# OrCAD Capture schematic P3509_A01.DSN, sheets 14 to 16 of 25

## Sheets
14 0011_BUTTON MCU: size Custom
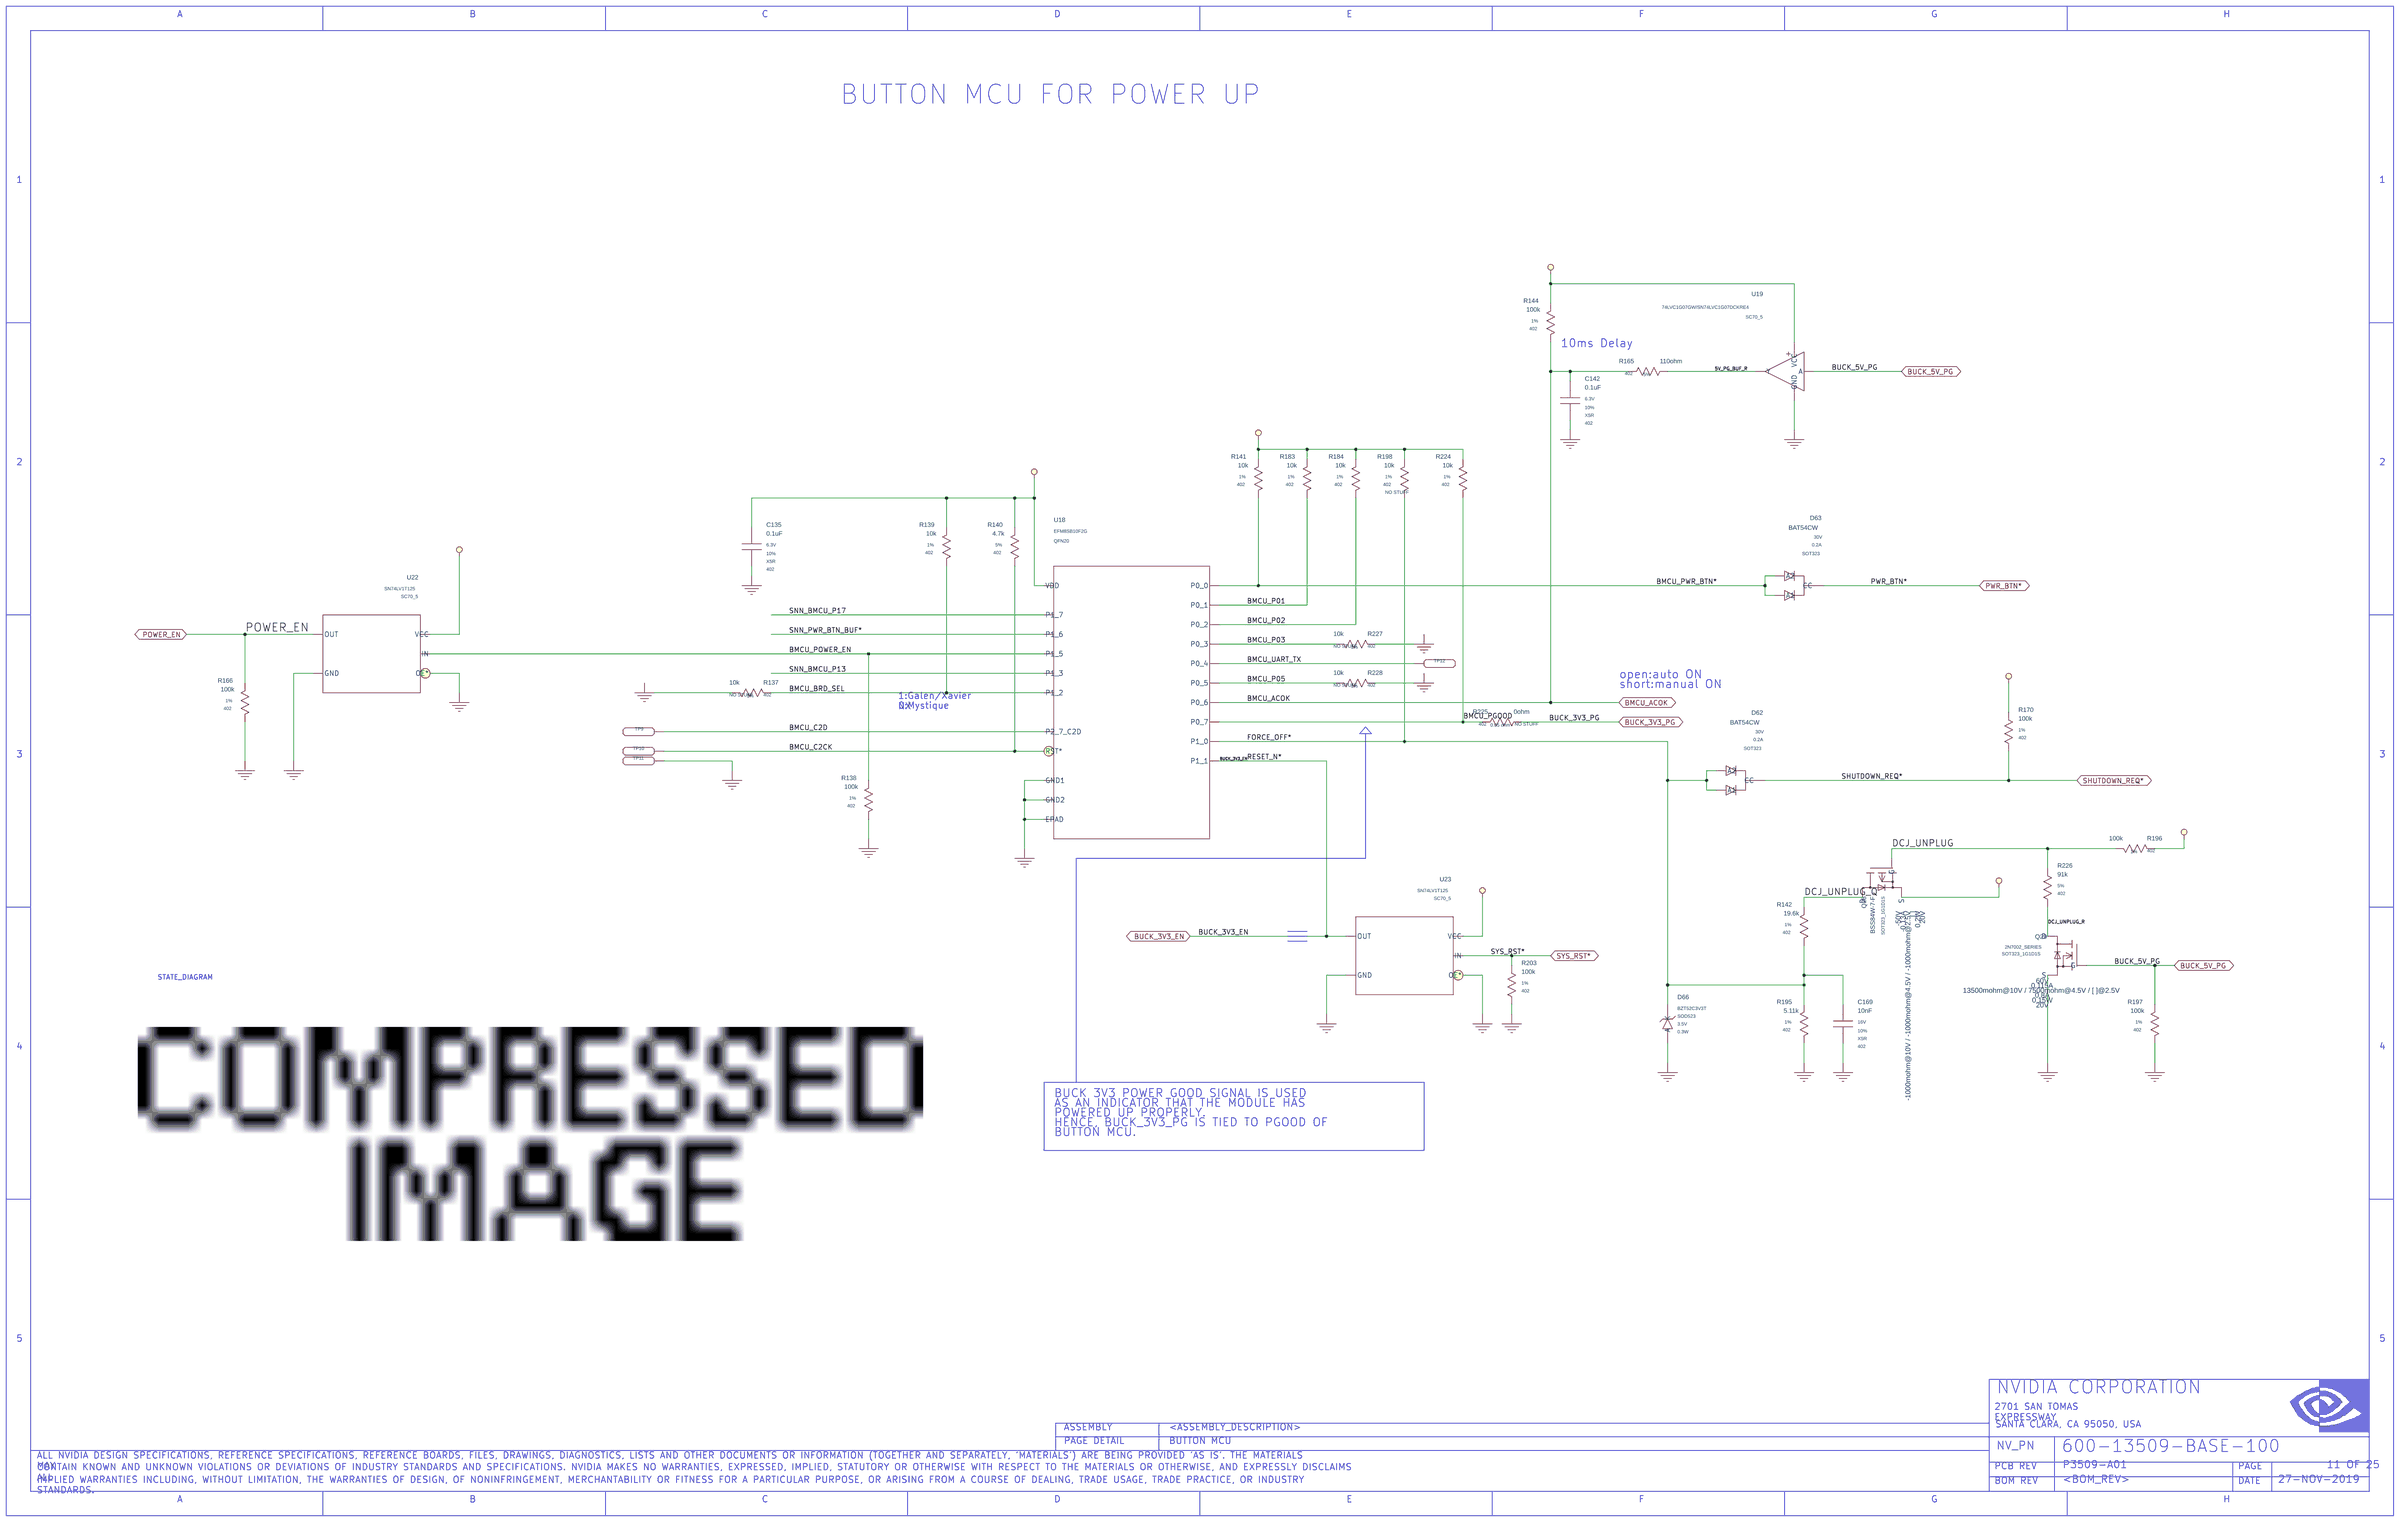
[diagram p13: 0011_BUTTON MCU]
15 0010_1V8 LDO & 3V3 AO Rails: size Custom
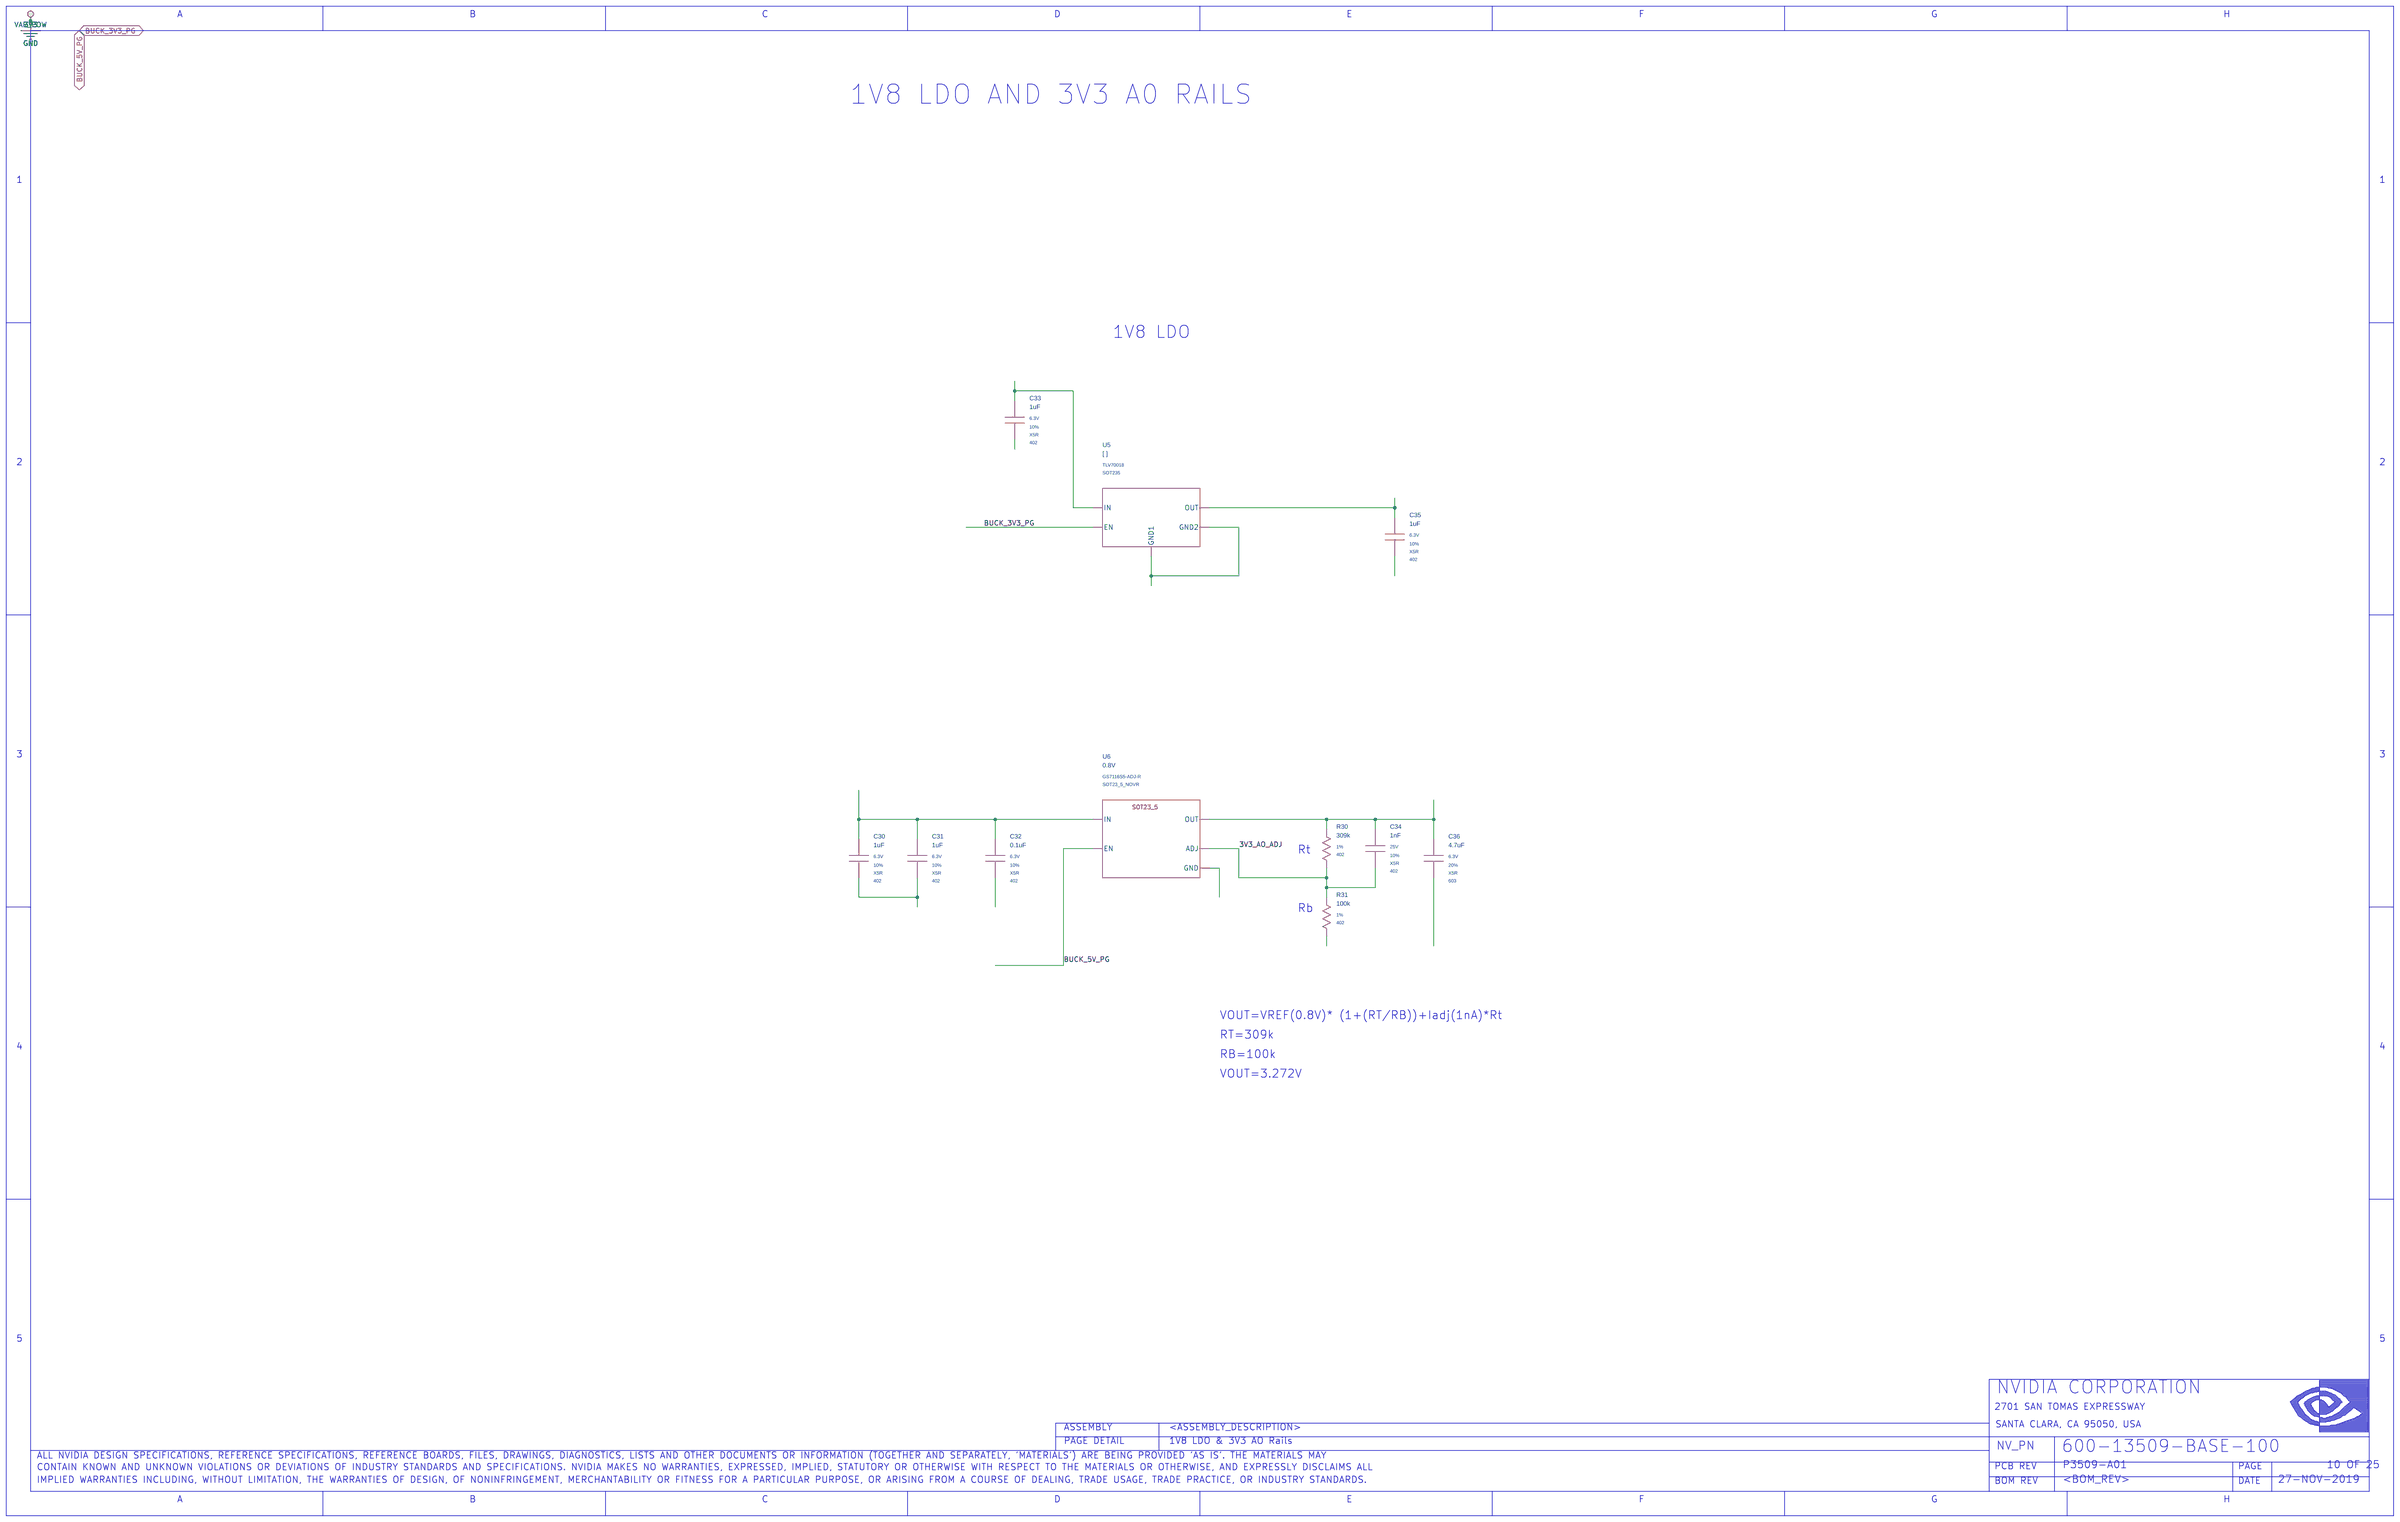
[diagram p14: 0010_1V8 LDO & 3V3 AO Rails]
16 0009_PRE-REG 3V3: size Custom
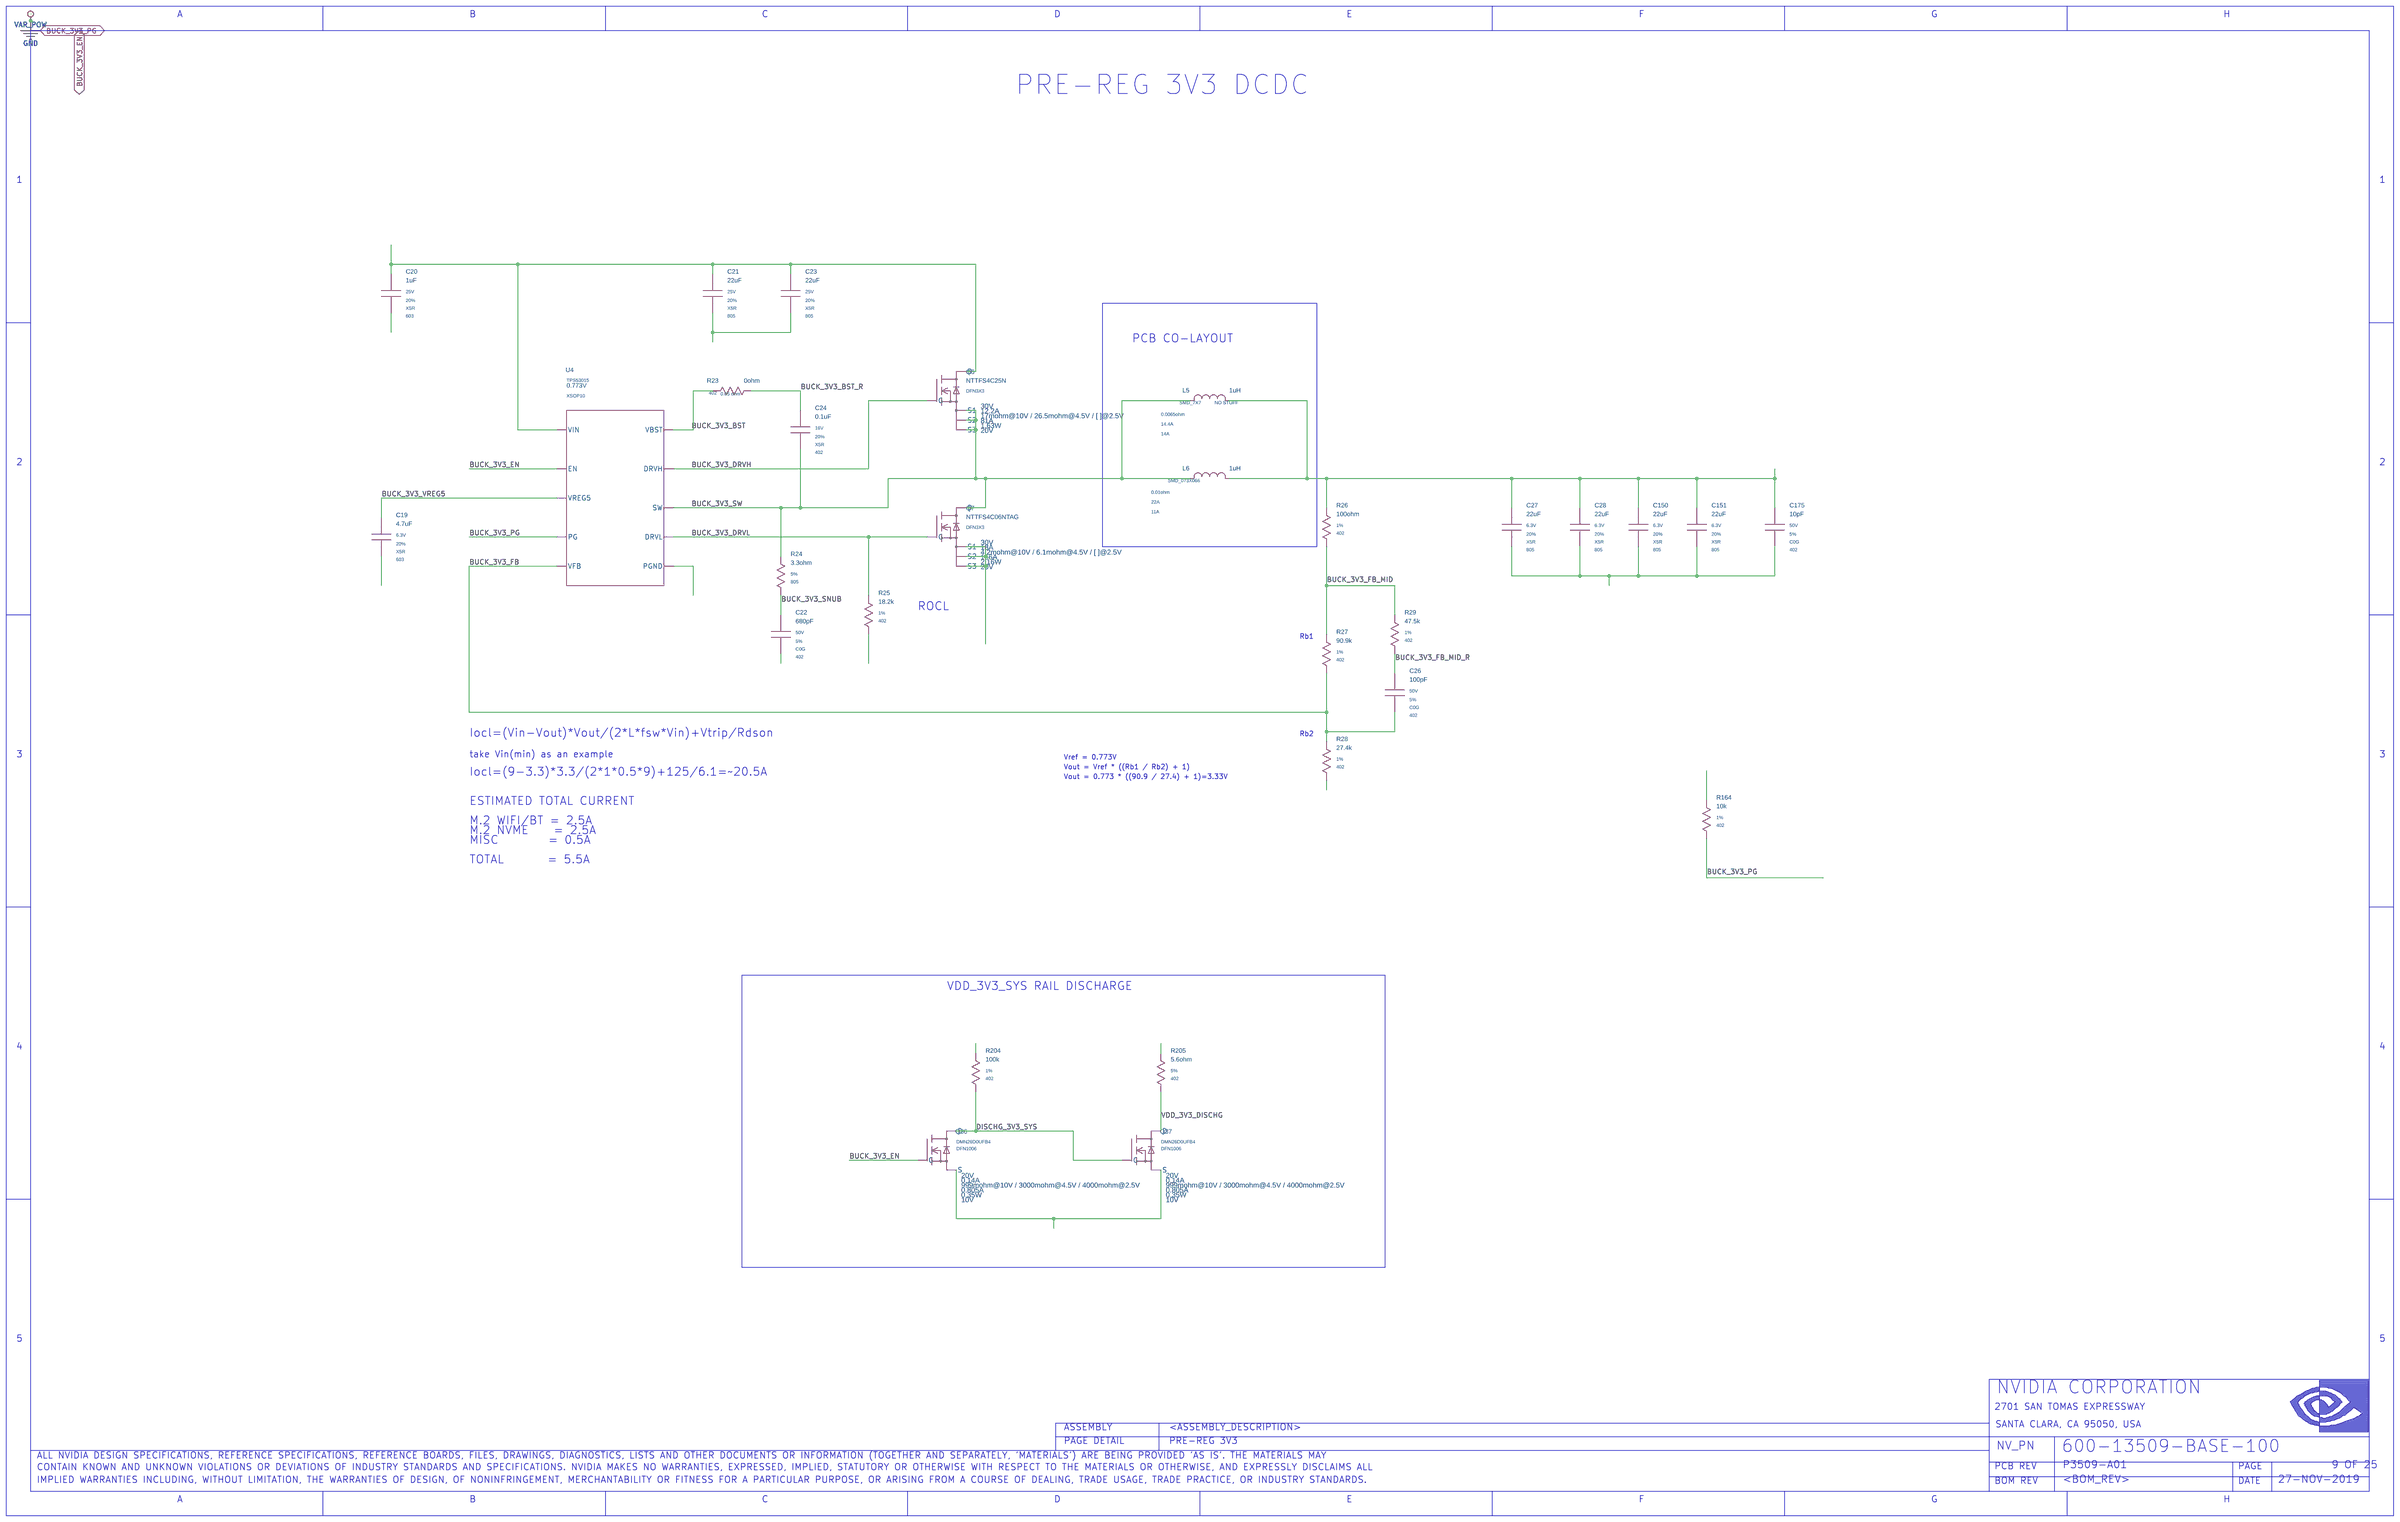
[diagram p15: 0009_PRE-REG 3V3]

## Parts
sheet 0009_PRE-REG 3V3
C19  4.7uF  [603]
C20  1uF  [603]
C21  22uF  [805]
C22  680pF  [402]
C23  22uF  [805]
C24  0.1uF  [402]
C26  100pF  [402]
C27  22uF  [805]
C28  22uF  [805]
C150  22uF  [805]
C151  22uF  [805]
C175  10pF  [402]
L5  1uH  [IND_NONRKO_SMD_071X065]
L6  1uH  [IND_NONRKO_SMD_073X066]
Q6  Q_FET_N_ENH  [MULTI_SMD_DFN08_SON08]
Q7  Q_FET_N_ENH  [MULTI_SMD_DFN08_SON08]
Q36  Q_FET_N_ENH  [DFET_003_SMD_010X006_B]
Q37  Q_FET_N_ENH  [DFET_003_SMD_010X006_B]
R23  0ohm  [402]
R24  3.3ohm  [805]
R25  18.2k  [402]
R26  100ohm  [402]
R27  90.9k  [402]
R28  27.4k  [402]
R29  47.5k  [402]
R164  10k  [402]
R204  100k  [402]
R205  5.6ohm  [402]
U4  0.773V  [XSOP10_P050_030X030]
sheet 0010_1V8 LDO & 3V3 AO Rails
C30  1uF  [402]
C31  1uF  [402]
C32  0.1uF  [402]
C33  1uF  [402]
C34  1nF  [402]
C35  1uF  [402]
C36  4.7uF  [603]
R30  309k  [402]
R31  100k  [402]
U5  [ ]  [SOT23_5]
U6  0.8V  [SOT23_5]
sheet 0011_BUTTON MCU
C135  0.1uF  [402]
C142  0.1uF  [402]
C169  10nF  [402]
D62  D_3PIN_CC  [SOT323]
D63  D_3PIN_CC  [SOT323]
D66  D_ZENER  [DIODE_SMD_SOD523_B]
Q28  Q_FET_P_ENH  [SOT323]
Q29  Q_FET_N_ENH  [SOT323]
R137  10k  [402]
R138  100k  [402]
R139  10k  [402]
R140  4.7k  [402]
R141  10k  [402]
R142  19.6k  [402]
R144  100k  [402]
R165  110ohm  [402]
R166  100k  [402]
R170  100k  [402]
R183  10k  [402]
R184  10k  [402]
R195  5.11k  [402]
R196  100k  [402]
R197  100k  [402]
R198  10k  [402]
R203  100k  [402]
R224  10k  [402]
R225  0ohm  [402]
R226  91k  [402]
R227  10k  [402]
R228  10k  [402]
TP9  LABTESTPOINT  [LTPT089C125D]
TP10  LABTESTPOINT  [LTPT089C125D]
TP11  LABTESTPOINT  [LTPT089C125D]
TP12  LABTESTPOINT  [LTPT089C125D]
U18  U_CPU_EFM8SB1  [QFN020Q_P050_0030_T018X018]
U19  U_BUF_OD  [SC70_5]
U22  U_LEVSHFT_3STATE  [SC70_5]
U23  U_LEVSHFT_3STATE  [SC70_5]

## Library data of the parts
C19 = C#1_v2: ASSEMBLY: PS_3V3; CDS_LIB: discrete; CDS_PART_NAME: C_0603-4.7UF,X5R,20%,6.3V,032-0886-000; CDS_PHYS_PART_NAME: C_0603-4.7UF,X5R,20%,6.3V,032-0886-000-032-0886-000,4.7UF; CDS_SEC: 1; CHIPS_PART_NAME: C; DEVICE_TYPENAME: C_0603-47UFX5R2063V032-0886-000-032-0886-00047UF; DRAWING: #NAME?; ESL: N/A; ESR: N/A; MAT: X5R; MAX_VOLTAGE: 6.3V; NV_PN: 032-0886-000; PATH: I34; PHYS_PAGE: 9; ROT: 0; SEC: 1; SIGNAL_MODEL: nv_cap; TOL: 20%; VER: 1; XY: (-10200,4900)
C20 = C#1_v2: ASSEMBLY: PS_3V3; CDS_LIB: discrete; CDS_PART_NAME: C_0603-1UF,X5R,20%,25V,032-0882-000; CDS_PHYS_PART_NAME: C_0603-1UF,X5R,20%,25V,032-0882-000-032-0882-000,1UF; CDS_SEC: 1; CHIPS_PART_NAME: C; DEVICE_TYPENAME: C_0603-1UFX5R2025V032-0882-000-032-0882-0001UF; DRAWING: #NAME?; MAT: X5R; MAX_VOLTAGE: 25V; NV_PN: 032-0882-000; PATH: I30; PHYS_PAGE: 9; ROT: 0; SEC: 1; SIGNAL_MODEL: nv_cap; TOL: 20%; VER: 1; XY: (-10150,6150)
C21 = C#1_v2: ASSEMBLY: PS_3V3; CDS_LIB: discrete; CDS_PART_NAME: C_0805-22UF,X5R,20%,25V,032-1308-000; CDS_PHYS_PART_NAME: C_0805-22UF,X5R,20%,25V,032-1308-000-032-1308-000,22UF; CDS_SEC: 1; CHIPS_PART_NAME: C; DEVICE_TYPENAME: C_0805-22UFX5R2025V032-1308-000-032-1308-00022UF; DRAWING: #NAME?; MAT: X5R; MAX_VOLTAGE: 25V; NV_PN: 032-1308-000; PATH: I13; PHYS_PAGE: 9; ROT: 0; SEC: 1; SIGNAL_MODEL: nv_cap; TOL: 20%; VER: 1; XY: (-8500,6150)
C22 = C#1_v2: ASSEMBLY: PS_3V3; CDS_LIB: discrete; CDS_PART_NAME: C_0402-680PF,C0G,5%,50V,035-0296-000; CDS_PHYS_PART_NAME: C_0402-680PF,C0G,5%,50V,035-0296-000-035-0296-000,680PF; CDS_SEC: 1; CHIPS_PART_NAME: C; DEVICE_TYPENAME: C_0402-680PFC0G550V035-0296-000-035-0296-000680PF; DRAWING: #NAME?; MAT: C0G; MAX_VOLTAGE: 50V; NV_PN: 035-0296-000; PATH: I26; PHYS_PAGE: 9; ROT: 0; SEC: 1; SIGNAL_MODEL: nv_cap; TOL: 5%; VER: 1; XY: (-8150,4400)
C23 = C#1_v2: ASSEMBLY: PS_3V3; CDS_LIB: discrete; CDS_PART_NAME: C_0805-22UF,X5R,20%,25V,032-1308-000; CDS_PHYS_PART_NAME: C_0805-22UF,X5R,20%,25V,032-1308-000-032-1308-000,22UF; CDS_SEC: 1; CHIPS_PART_NAME: C; DEVICE_TYPENAME: C_0805-22UFX5R2025V032-1308-000-032-1308-00022UF; DRAWING: #NAME?; MAT: X5R; MAX_VOLTAGE: 25V; NV_PN: 032-1308-000; PATH: I11; PHYS_PAGE: 9; ROT: 0; SEC: 1; SIGNAL_MODEL: nv_cap; TOL: 20%; VER: 1; XY: (-8100,6150)
C24 = C#1_v2: ASSEMBLY: PS_3V3; CDS_LIB: discrete; CDS_PART_NAME: C_0402-0.1UF,X5R,20%,16V,032-0877-000; CDS_PHYS_PART_NAME: C_0402-0.1UF,X5R,20%,16V,032-0877-000-0.1UF,032-0877-000; CDS_SEC: 1; CHIPS_PART_NAME: C; DEVICE_TYPENAME: C_0402-01UFX5R2016V032-0877-000-01UF032-0877-000; DRAWING: #NAME?; MAT: X5R; MAX_VOLTAGE: 16V; NV_PN: 032-0877-000; PATH: I12; PHYS_PAGE: 9; ROT: 0; SEC: 1; TOL: 20%; VER: 1; XY: (-8050,5450)
C26 = C#1_v2: ASSEMBLY: PS_3V3; CDS_LIB: discrete; CDS_PART_NAME: C_0402-100PF,C0G,5%,50V,035-0012-000; CDS_PHYS_PART_NAME: C_0402-100PF,C0G,5%,50V,035-0012-000-035-0012-000,100PF; CDS_SEC: 1; CHIPS_PART_NAME: C; DEVICE_TYPENAME: C_0402-100PFC0G550V035-0012-000-035-0012-000100PF; DRAWING: #NAME?; MAT: C0G; MAX_VOLTAGE: 50V; NV_PN: 035-0012-000; PATH: I19; PHYS_PAGE: 9; ROT: 0; SEC: 1; SIGNAL_MODEL: nv_cap; TOL: 5%; VER: 1; XY: (-5000,4100)
C27 = C#1_v2: ASSEMBLY: PS_3V3; CDS_LIB: discrete; CDS_PART_NAME: C_0805-22UF,X5R,20%,6.3V,039-0127-000; CDS_PHYS_PART_NAME: C_0805-22UF,X5R,20%,6.3V,039-0127-000-039-0127-000,22UF; CDS_SEC: 1; CHIPS_PART_NAME: C; DEVICE_TYPENAME: C_0805-22UFX5R2063V039-0127-000-039-0127-00022UF; DRAWING: #NAME?; MAT: X5R; MAX_VOLTAGE: 6.3V; NV_PN: 039-0127-000; PATH: I6; PHYS_PAGE: 9; ROT: 0; SEC: 1; SIGNAL_MODEL: nv_cap; TOL: 20%; VER: 1; XY: (-4400,4950)
C28 = C#1_v2: ASSEMBLY: PS_3V3; CDS_LIB: discrete; CDS_PART_NAME: C_0805-22UF,X5R,20%,6.3V,039-0127-000; CDS_PHYS_PART_NAME: C_0805-22UF,X5R,20%,6.3V,039-0127-000-039-0127-000,22UF; CDS_SEC: 1; CHIPS_PART_NAME: C; DEVICE_TYPENAME: C_0805-22UFX5R2063V039-0127-000-039-0127-00022UF; DRAWING: #NAME?; MAT: X5R; MAX_VOLTAGE: 6.3V; NV_PN: 039-0127-000; PATH: I5; PHYS_PAGE: 9; ROT: 0; SEC: 1; SIGNAL_MODEL: nv_cap; TOL: 20%; VER: 1; XY: (-4050,4950)
C150 = C#1_v2: ASSEMBLY: PS_3V3; CDS_LIB: discrete; CDS_PART_NAME: C_0805-22UF,X5R,20%,6.3V,039-0127-000; CDS_PHYS_PART_NAME: C_0805-22UF,X5R,20%,6.3V,039-0127-000-039-0127-000,22UF; CDS_SEC: 1; CHIPS_PART_NAME: C; DEVICE_TYPENAME: C_0805-22UFX5R2063V039-0127-000-039-0127-00022UF; DRAWING: #NAME?; MAT: X5R; MAX_VOLTAGE: 6.3V; NV_PN: 039-0127-000; PATH: I41; PHYS_PAGE: 9; ROT: 0; SEC: 1; SIGNAL_MODEL: nv_cap; TOL: 20%; VER: 1; XY: (-3750,4950)
C151 = C#1_v2: ASSEMBLY: PS_3V3; CDS_LIB: discrete; CDS_PART_NAME: C_0805-22UF,X5R,20%,6.3V,039-0127-000; CDS_PHYS_PART_NAME: C_0805-22UF,X5R,20%,6.3V,039-0127-000-039-0127-000,22UF; CDS_SEC: 1; CHIPS_PART_NAME: C; DEVICE_TYPENAME: C_0805-22UFX5R2063V039-0127-000-039-0127-00022UF; DRAWING: #NAME?; MAT: X5R; MAX_VOLTAGE: 6.3V; NV_PN: 039-0127-000; PATH: I42; PHYS_PAGE: 9; ROT: 0; SEC: 1; SIGNAL_MODEL: nv_cap; TOL: 20%; VER: 1; XY: (-3450,4950)
C175 = C#1_v2: ASSEMBLY: PS_3V3; CDS_LIB: discrete; CDS_PART_NAME: C_0402-10PF,C0G,5%,50V,035-0011-000; CDS_PHYS_PART_NAME: C_0402-10PF,C0G,5%,50V,035-0011-000-035-0011-000,10PF; CDS_SEC: 1; CHIPS_PART_NAME: C; DEVICE_TYPENAME: C_0402-10PFC0G550V035-0011-000-035-0011-00010PF; DRAWING: #NAME?; MAT: C0G; MAX_VOLTAGE: 50V; NV_PN: 035-0011-000; PATH: I45; PHYS_PAGE: 9; ROT: 0; SEC: 1; SIGNAL_MODEL: nv_cap; TOL: 5%; VER: 1; XY: (-3050,4950)
L5 = L: ASSEMBLY: PS_3V3; CDS_LIB: discrete; CDS_PART_NAME: L_SMD_7X7-1UH,IRON POWDER CORE,20%,14A,14.4A,0.0065OHM,0@0HZ,3MHZ,130-0996-000; CDS_PHYS_PART_NAME: L_SMD_7X7-1UH,IRON POWDER CORE,20%,14A,14.4A,0.0065OHM,0@0HZ,3MHZ,130-0996-000-130-0996-000,1UH; CDS_SEC: 1; CONTINUOUS_CURRENT: 14A; DC_RESISTANCE: 0.0065ohm; DEVICE_TYPENAME: L_SMD_7X7-1UHIRONPOWDERCORE2014A144A00065OHM00HZ3MHZ130-0996-000-130-0996-0001UH; DRAWING: #NAME?; MAT: Iron powder core; MAX_CURRENT: 14.4A; NV_PN: 130-0996-000; PACK_TYPE: SMD_7X7; PATH: I7; PHYS_PAGE: 9; Q: 0@0Hz; ROT: 0; SEC: 1; SELF_RESONANCE_FREQ: 3MHz; SIGNAL_MODEL: nv_ind; SKU: NO STUFF; TOL: 20%; VER: 1; XY: (-5950,5600)
L6 = L: ASSEMBLY: PS_3V3; CDS_LIB: discrete; CDS_PART_NAME: L_SMD_073X066-1UH,CARBONYL POWDER,20%,11A,22A,0.01OHM,[ ]@[ ],[ ],130-0776-000; CDS_PHYS_PART_NAME: L_SMD_073X066-1UH,CARBONYL POWDER,20%,11A,22A,0.01OHM,[ ]@[ ],[ ],130-0776-000-130-0776-000,1UH; CDS_SEC: 1; CONTINUOUS_CURRENT: 11A; DC_RESISTANCE: 0.01ohm; DEVICE_TYPENAME: L_SMD_073X066-1UHCARBONYLPOWDER2011A22A001OHM130-0776-000-130-0776-0001UH; DRAWING: #NAME?; MAT: Carbonyl Powder; MAX_CURRENT: 22A; NV_PN: 130-0776-000; PACK_TYPE: SMD_073X066; PATH: I8; PHYS_PAGE: 9; Q: [ ]@[ ]; ROT: 0; SEC: 1; SELF_RESONANCE_FREQ: [ ]; SIGNAL_MODEL: nv_ind; TOL: 20%; VER: 1; XY: (-5950,5200)
Q6 = Q_FET_N_ENH#2: ASSEMBLY: PS_3V3; CDS_LIB: discrete; CDS_PART_NAME: Q_FET_N_ENH_DFN3X3-NTTFS4C25N,30V,17MOHM@10V / 26.5MOHM@4.5V / [ ]@2.5V,12.2A,81A,20V,1.63W,10.3NC@10V / 5.1NC@4.5V / [ ]@2.5VA; CDS_PHYS_PART_NAME: Q_FET_N_ENH_DFN3X3-NTTFS4C25N,30V,17MOHM@10V / 26.5MOHM@4.5V / [ ]@2.5V,12.2A,81A,20V,1.63W,10.3NC@10V / 5.1NC@4.5V / [ ]@2.5VB; CDS_SEC: 1; CONTINUOUS_CURRENT: 12.2A; DEVICE_TYPENAME: Q_FET_N_ENH_DFN3X3-NTTFS4C25N30V17MOHM10V265MOHM45V25V122A81A20V163W103NC10V51NC45V25VB; DRAWING: #NAME?; MAX_CURRENT: 81A; MAX_VOLTAGE: 30V; MAX_WATTAGE: 1.63W; NV_NAME: NTTFS4C25N; NV_PN: 300-1021-000; PACK_TYPE: DFN3X3; PATH: I9; PHYS_PAGE: 9; Q_G: 10.3nC@10V / 5.1nC@4.5V / [ ]@2.5V; ROT: 0; R_DS_ON: 17mohm@10V / 26.5mohm@4.5V / [ ]@2.5V; SEC: 1; VER: 5; V_BE_GS: 20V; XY: (-7300,5650)
Q7 = Q_FET_N_ENH#2: ASSEMBLY: PS_3V3; CDS_LIB: discrete; CDS_PART_NAME: Q_FET_N_ENH_DFN3X3-NTTFS4C06NTAG,30V,4.2MOHM@10V / 6.1MOHM@4.5V / [ ]@2.5V,18A,166A,20V,2.16W,26NC@10V / 11.6NC@4.5V / [ ]@2.5A; CDS_PHYS_PART_NAME: Q_FET_N_ENH_DFN3X3-NTTFS4C06NTAG,30V,4.2MOHM@10V / 6.1MOHM@4.5V / [ ]@2.5V,18A,166A,20V,2.16W,26NC@10V / 11.6NC@4.5V / [ ]@2.5B; CDS_SEC: 1; CONTINUOUS_CURRENT: 18A; DEVICE_TYPENAME: Q_FET_N_ENH_DFN3X3-NTTFS4C06NTAG30V42MOHM10V61MOHM45V25V18A166A20V216W26NC10V116NC45V25B; DRAWING: #NAME?; MAX_CURRENT: 166A; MAX_VOLTAGE: 30V; MAX_WATTAGE: 2.16W; NV_NAME: NTTFS4C06NTAG; NV_PN: 300-0284-000; PACK_TYPE: DFN3X3; PATH: I1; PHYS_PAGE: 9; Q_G: 26nC@10V / 11.6nC@4.5V / [ ]@2.5V; ROT: 0; R_DS_ON: 4.2mohm@10V / 6.1mohm@4.5V / [ ]@2.5V; SEC: 1; VER: 5; V_BE_GS: 20V; XY: (-7300,4950)
Q36 = Q_FET_N_ENH#1: ASSEMBLY: PS_3V3; CDS_LIB: discrete; CDS_PART_NAME: Q_FET_N_ENH_DFN1006-DMN26D0UFB4,20V,999MOHM@10V / 3000MOHM@4.5V / 4000MOHM@2.5V,0.14A,0.805A,10V,0.35W,999NC@10V / 0NC@4.5V / A; CDS_PHYS_PART_NAME: Q_FET_N_ENH_DFN1006-DMN26D0UFB4,20V,999MOHM@10V / 3000MOHM@4.5V / 4000MOHM@2.5V,0.14A,0.805A,10V,0.35W,999NC@10V / 0NC@4.5V / B; CDS_SEC: 1; CONTINUOUS_CURRENT: 0.14A; CaptureCellPackProp: Q_FET_N_ENH##1; DEVICE_TYPENAME: Q_FET_N_ENH_DFN1006-DMN26D0UFB420V999MOHM10V3000MOHM45V4000MOHM25V014A0805A10V035W999NC10V0NC45VB; DRAWING: #NAME?; MAX_CURRENT: 0.805A; MAX_VOLTAGE: 20V; MAX_WATTAGE: 0.35W; NV_NAME: DMN26D0UFB4; NV_PN: 300-0868-000; PACK_TYPE: DFN1006; PATH: I46; PHYS_PAGE: 9; Q_G: 999nC@10V / 0nC@4.5V / 999nC@2.5V; ROT: 0; R_DS_ON: 999mohm@10V / 3000mohm@4.5V / 4000mohm@2.5V; SEC: 1; VER: 2; V_BE_GS: 10V; XY: (-7350,1750)
Q37 = Q_FET_N_ENH#1: ASSEMBLY: PS_3V3; CDS_LIB: discrete; CDS_PART_NAME: Q_FET_N_ENH_DFN1006-DMN26D0UFB4,20V,999MOHM@10V / 3000MOHM@4.5V / 4000MOHM@2.5V,0.14A,0.805A,10V,0.35W,999NC@10V / 0NC@4.5V / A; CDS_PHYS_PART_NAME: Q_FET_N_ENH_DFN1006-DMN26D0UFB4,20V,999MOHM@10V / 3000MOHM@4.5V / 4000MOHM@2.5V,0.14A,0.805A,10V,0.35W,999NC@10V / 0NC@4.5V / B; CDS_SEC: 1; CONTINUOUS_CURRENT: 0.14A; CaptureCellPackProp: Q_FET_N_ENH##1; DEVICE_TYPENAME: Q_FET_N_ENH_DFN1006-DMN26D0UFB420V999MOHM10V3000MOHM45V4000MOHM25V014A0805A10V035W999NC10V0NC45VB; DRAWING: #NAME?; MAX_CURRENT: 0.805A; MAX_VOLTAGE: 20V; MAX_WATTAGE: 0.35W; NV_NAME: DMN26D0UFB4; NV_PN: 300-0868-000; PACK_TYPE: DFN1006; PATH: I47; PHYS_PAGE: 9; Q_G: 999nC@10V / 0nC@4.5V / 999nC@2.5V; ROT: 0; R_DS_ON: 999mohm@10V / 3000mohm@4.5V / 4000mohm@2.5V; SEC: 1; VER: 2; V_BE_GS: 10V; XY: (-6300,1750)
R23 = R#1: ASSEMBLY: PS_3V3; CDS_LIB: discrete; CDS_PART_NAME: R_0402-0OHM,0.05 OHM,62.5MW,195-2655-000; CDS_PHYS_PART_NAME: R_0402-0OHM,0.05 OHM,62.5MW,195-2655-000-0OHM,195-2655-000; CDS_SEC: 1; CHIPS_PART_NAME: R; DEVICE_TYPENAME: R_0402-0OHM005OHM625MW195-2655-000-0OHM195-2655-000; DRAWING: #NAME?; MAX_WATTAGE: 62.5mW; NV_PN: 195-2655-000; PATH: I15; PHYS_PAGE: 9; ROT: 0; SEC: 1; TOL: 0.05 ohm; VER: 1; XY: (-8400,5650)
R24 = R: ASSEMBLY: PS_3V3; CDS_LIB: discrete; CDS_PART_NAME: R_0805-3.3OHM,5 %,0.125W,195-1602-000; CDS_PHYS_PART_NAME: R_0805-3.3OHM,5 %,0.125W,195-1602-000-195-1602-000,3.3OHM; CDS_SEC: 1; DEVICE_TYPENAME: R_0805-33OHM50125W195-1602-000-195-1602-00033OHM; DRAWING: #NAME?; MAX_WATTAGE: 0.125W; NV_PN: 195-1602-000; PATH: I25; PHYS_PAGE: 9; ROT: 0; SEC: 1; SIGNAL_MODEL: nv_res; TOL: 5%; VER: 2; XY: (-8150,4700)
R25 = R: ASSEMBLY: PS_3V3; CDS_LIB: discrete; CDS_PART_NAME: R_0402-18.2K,1 %,62.5MW,195-0130-000; CDS_PHYS_PART_NAME: R_0402-18.2K,1 %,62.5MW,195-0130-000-18.2K,195-0130-000; CDS_SEC: 1; DEVICE_TYPENAME: R_0402-182K1625MW195-0130-000-182K195-0130-000; DRAWING: #NAME?; MAX_WATTAGE: 62.5mW; NV_PN: 195-0130-000; PATH: I23; PHYS_PAGE: 9; ROT: 0; SEC: 1; SIGNAL_MODEL: nv_res; TOL: 1%; VER: 2; XY: (-7700,4500)
R26 = R: ASSEMBLY: PS_3V3; CDS_LIB: discrete; CDS_PART_NAME: R_0402-100OHM,1 %,62.5MW,195-0002-000; CDS_PHYS_PART_NAME: R_0402-100OHM,1 %,62.5MW,195-0002-000-100OHM,195-0002-000; CDS_SEC: 1; DEVICE_TYPENAME: R_0402-100OHM1625MW195-0002-000-100OHM195-0002-000; DRAWING: #NAME?; MAX_WATTAGE: 62.5mW; NV_PN: 195-0002-000; PATH: I17; PHYS_PAGE: 9; ROT: 0; SEC: 1; SIGNAL_MODEL: nv_res; TOL: 1%; VER: 2; XY: (-5350,4950)
R27 = R: ASSEMBLY: PS_3V3; CDS_LIB: discrete; CDS_PART_NAME: R_0402-90.9K,1 %,62.5MW,195-0465-000; CDS_PHYS_PART_NAME: R_0402-90.9K,1 %,62.5MW,195-0465-000-195-0465-000,90.9K; CDS_SEC: 1; DEVICE_TYPENAME: R_0402-909K1625MW195-0465-000-195-0465-000909K; DRAWING: #NAME?; MAX_WATTAGE: 62.5mW; NV_PN: 195-0465-000; PATH: I18; PHYS_PAGE: 9; ROT: 0; SEC: 1; TOL: 1%; VER: 2; XY: (-5350,4300)
R28 = R: ASSEMBLY: PS_3V3; CDS_LIB: discrete; CDS_PART_NAME: R_0402-27.4K,1 %,62.5MW,195-0215-000; CDS_PHYS_PART_NAME: R_0402-27.4K,1 %,62.5MW,195-0215-000-195-0215-000,27.4K; CDS_SEC: 1; DEVICE_TYPENAME: R_0402-274K1625MW195-0215-000-195-0215-000274K; DRAWING: #NAME?; MAX_WATTAGE: 62.5mW; NV_PN: 195-0215-000; PATH: I21; PHYS_PAGE: 9; ROT: 0; SEC: 1; TOL: 1%; VER: 2; XY: (-5350,3750)
R29 = R: ASSEMBLY: PS_3V3; CDS_LIB: discrete; CDS_PART_NAME: R_0402-47.5K,1 %,62.5MW,195-0330-000; CDS_PHYS_PART_NAME: R_0402-47.5K,1 %,62.5MW,195-0330-000-195-0330-000,47.5K; CDS_SEC: 1; DEVICE_TYPENAME: R_0402-475K1625MW195-0330-000-195-0330-000475K; DRAWING: #NAME?; MAX_WATTAGE: 62.5mW; NV_PN: 195-0330-000; PATH: I16; PHYS_PAGE: 9; ROT: 0; SEC: 1; SIGNAL_MODEL: nv_res; TOL: 1%; VER: 2; XY: (-5000,4400)
R164 = R: ASSEMBLY: PS_3V3; CDS_LIB: discrete; CDS_PART_NAME: R_0402-10K,1 %,62.5MW,195-0004-000; CDS_PHYS_PART_NAME: R_0402-10K,1 %,62.5MW,195-0004-000-10K,195-0004-000; CDS_SEC: 1; DEVICE_TYPENAME: R_0402-10K1625MW195-0004-000-10K195-0004-000; DRAWING: #NAME?; MAX_WATTAGE: 62.5mW; NV_PN: 195-0004-000; PATH: I38; PHYS_PAGE: 9; ROT: 0; SEC: 1; SIGNAL_MODEL: nv_res; TOL: 1%; VER: 2; XY: (-3400,3450)
R204 = R: ASSEMBLY: PS_3V3; CDS_LIB: discrete; CDS_PART_NAME: R_0402-100K,1 %,62.5MW,195-0005-000; CDS_PHYS_PART_NAME: R_0402-100K,1 %,62.5MW,195-0005-000-100K,195-0005-000; CDS_SEC: 1; DEVICE_TYPENAME: R_0402-100K1625MW195-0005-000-100K195-0005-000; DRAWING: #NAME?; MAX_WATTAGE: 62.5mW; NV_PN: 195-0005-000; PATH: I48; PHYS_PAGE: 9; ROT: 0; SEC: 1; TOL: 1%; VER: 2; XY: (-7150,2150)
R205 = R: ASSEMBLY: PS_3V3; CDS_LIB: discrete; CDS_PART_NAME: R_0402-5.6OHM,5 %,62.5MW,195-0609-000; CDS_PHYS_PART_NAME: R_0402-5.6OHM,5 %,62.5MW,195-0609-000-195-0609-000,5.6OHM; CDS_SEC: 1; DEVICE_TYPENAME: R_0402-56OHM5625MW195-0609-000-195-0609-00056OHM; DRAWING: #NAME?; MAX_WATTAGE: 62.5mW; NV_PN: 195-0609-000; PATH: I51; PHYS_PAGE: 9; ROT: 0; SEC: 1; TOL: 5%; VER: 2; XY: (-6200,2150)
U4 = U_SWREG_TPS53015: ASSEMBLY: PS_3V3; CDS_LIB: power_supply; CDS_PART_NAME: U_SWREG_TPS53015_XSOP10-TPS53015,BUCK,1PH,500KHZ,NONE,0.77V..7V,1%,0.773V,28V,10A,50W,316-0314-000; CDS_PHYS_PART_NAME: U_SWREG_TPS53015_XSOP10-TPS53015,BUCK,1PH,500KHZ,NONE,0.77V..7V,1%,0.773V,28V,10A,50W,316-0314-000-0.773V,316-0314-000; CDS_SEC: 1; DEVICE_TYPENAME: U_SWREG_TPS53015_XSOP10-TPS53015BUCK1PH500KHZNONE077V7V10773V28V10A50W316-0314-000-0773V316-0314-000; DRAWING: #NAME?; MAX_CURRENT: 10A; MAX_VOLTAGE: 28V; MAX_WATTAGE: 50W; MODE: Buck; NV_NAME: TPS53015; NV_PN: 316-0314-000; OUTPUT_VOLTAGE: 0.77V..7V; PACK_TYPE: XSOP10; PATH: I33; PHASES: 1Ph; PHYS_PAGE: 9; PROGRAMMABLE: None; ROT: 0; SEC: 1; SWITCHING_FREQ: 500KHz; TOL: 1%; VER: 1; XY: (-9000,5100)
C30 = C#1_v2: ASSEMBLY: 3V3_AO; CDS_LIB: discrete; CDS_PART_NAME: C_0402-1UF,X5R,10%,6.3V,039-0008-000; CDS_PHYS_PART_NAME: C_0402-1UF,X5R,10%,6.3V,039-0008-000-039-0008-000,1UF; CDS_SEC: 1; CHIPS_PART_NAME: C; DEVICE_TYPENAME: C_0402-1UFX5R1063V039-0008-000-039-0008-0001UF; DRAWING: #NAME?; MAT: X5R; MAX_VOLTAGE: 6.3V; NV_PN: 039-0008-000; PATH: I24; PHYS_PAGE: 10; ROT: 0; SEC: 1; SIGNAL_MODEL: nv_cap; TOL: 10%; VER: 1; XY: (-7750,3250)
C31 = C#1_v2: ASSEMBLY: 3V3_AO; CDS_LIB: discrete; CDS_PART_NAME: C_0402-1UF,X5R,10%,6.3V,039-0008-000; CDS_PHYS_PART_NAME: C_0402-1UF,X5R,10%,6.3V,039-0008-000-039-0008-000,1UF; CDS_SEC: 1; CHIPS_PART_NAME: C; DEVICE_TYPENAME: C_0402-1UFX5R1063V039-0008-000-039-0008-0001UF; DRAWING: #NAME?; MAT: X5R; MAX_VOLTAGE: 6.3V; NV_PN: 039-0008-000; PATH: I23; PHYS_PAGE: 10; ROT: 0; SEC: 1; SIGNAL_MODEL: nv_cap; TOL: 10%; VER: 1; XY: (-7450,3250)
C32 = C#1_v2: ASSEMBLY: 3V3_AO; CDS_LIB: discrete; CDS_PART_NAME: C_0402-0.1UF,X5R,10%,6.3V,039-0007-000; CDS_PHYS_PART_NAME: C_0402-0.1UF,X5R,10%,6.3V,039-0007-000-0.1UF,039-0007-000; CDS_SEC: 1; CHIPS_PART_NAME: C; DEVICE_TYPENAME: C_0402-01UFX5R1063V039-0007-000-01UF039-0007-000; DRAWING: #NAME?; MAT: X5R; MAX_VOLTAGE: 6.3V; NV_PN: 039-0007-000; PATH: I20; PHYS_PAGE: 10; ROT: 0; SEC: 1; SIGNAL_MODEL: nv_cap; TOL: 10%; VER: 1; XY: (-7050,3250)
C33 = C#1_v2: ASSEMBLY: 1V8_LDO; CDS_LIB: discrete; CDS_PART_NAME: C_0402-1UF,X5R,10%,6.3V,039-0008-000; CDS_PHYS_PART_NAME: C_0402-1UF,X5R,10%,6.3V,039-0008-000-039-0008-000,1UF; CDS_SEC: 1; CHIPS_PART_NAME: C; DEVICE_TYPENAME: C_0402-1UFX5R1063V039-0008-000-039-0008-0001UF; DRAWING: #NAME?; MAT: X5R; MAX_VOLTAGE: 6.3V; NV_PN: 039-0008-000; PATH: I7; PHYS_PAGE: 10; ROT: 0; SEC: 1; SIGNAL_MODEL: nv_cap; TOL: 10%; VER: 1; XY: (-6950,5500)
C34 = C#1_v2: ASSEMBLY: 3V3_AO; CDS_LIB: discrete; CDS_PART_NAME: C_0402-1NF,X5R,10%,25V,039-0028-000; CDS_PHYS_PART_NAME: C_0402-1NF,X5R,10%,25V,039-0028-000-039-0028-000,1NF; CDS_SEC: 1; CHIPS_PART_NAME: C; DEVICE_TYPENAME: C_0402-1NFX5R1025V039-0028-000-039-0028-0001NF; DRAWING: #NAME?; MAT: X5R; MAX_VOLTAGE: 25V; NV_PN: 039-0028-000; PATH: I14; PHYS_PAGE: 10; ROT: 0; SEC: 1; SIGNAL_MODEL: nv_cap; TOL: 10%; VER: 1; XY: (-5100,3300)
C35 = C#1_v2: ASSEMBLY: 1V8_LDO; CDS_LIB: discrete; CDS_PART_NAME: C_0402-1UF,X5R,10%,6.3V,039-0008-000; CDS_PHYS_PART_NAME: C_0402-1UF,X5R,10%,6.3V,039-0008-000-039-0008-000,1UF; CDS_SEC: 1; CHIPS_PART_NAME: C; DEVICE_TYPENAME: C_0402-1UFX5R1063V039-0008-000-039-0008-0001UF; DRAWING: #NAME?; MAT: X5R; MAX_VOLTAGE: 6.3V; NV_PN: 039-0008-000; PATH: I3; PHYS_PAGE: 10; ROT: 0; SEC: 1; SIGNAL_MODEL: nv_cap; TOL: 10%; VER: 1; XY: (-5000,4900)
C36 = C#1_v2: ASSEMBLY: 3V3_AO; CDS_LIB: discrete; CDS_PART_NAME: C_0603-4.7UF,X5R,20%,6.3V,032-0886-000; CDS_PHYS_PART_NAME: C_0603-4.7UF,X5R,20%,6.3V,032-0886-000-032-0886-000,4.7UF; CDS_SEC: 1; CHIPS_PART_NAME: C; DEVICE_TYPENAME: C_0603-47UFX5R2063V032-0886-000-032-0886-00047UF; DRAWING: #NAME?; MAT: X5R; MAX_VOLTAGE: 6.3V; NV_PN: 032-0886-000; PATH: I13; PHYS_PAGE: 10; ROT: 0; SEC: 1; SIGNAL_MODEL: nv_cap; TOL: 20%; VER: 1; XY: (-4800,3250)
R30 = R: ASSEMBLY: 3V3_AO; CDS_LIB: discrete; CDS_PART_NAME: R_0402-309K,1 %,62.5MW,195-0241-000; CDS_PHYS_PART_NAME: R_0402-309K,1 %,62.5MW,195-0241-000-195-0241-000,309K; CDS_SEC: 1; DEVICE_TYPENAME: R_0402-309K1625MW195-0241-000-195-0241-000309K; DRAWING: #NAME?; MAX_WATTAGE: 62.5mW; NV_PN: 195-0241-000; PATH: I16; PHYS_PAGE: 10; ROT: 0; SEC: 1; SIGNAL_MODEL: nv_res; TOL: 1%; VER: 2; XY: (-5350,3300)
R31 = R: ASSEMBLY: 3V3_AO; CDS_LIB: discrete; CDS_PART_NAME: R_0402-100K,1 %,62.5MW,195-0005-000; CDS_PHYS_PART_NAME: R_0402-100K,1 %,62.5MW,195-0005-000-100K,195-0005-000; CDS_SEC: 1; DEVICE_TYPENAME: R_0402-100K1625MW195-0005-000-100K195-0005-000; DRAWING: #NAME?; MAX_WATTAGE: 62.5mW; NV_PN: 195-0005-000; PATH: I18; PHYS_PAGE: 10; ROT: 0; SEC: 1; SIGNAL_MODEL: nv_res; TOL: 1%; VER: 2; XY: (-5350,2950)
U5 = U_VREG_5PIN: ASSEMBLY: 1V8_LDO; CDS_LIB: power_supply; CDS_PART_NAME: U_VREG_5PIN_SOT235-TLV70018,LOW DROP OUT/FIXED,0.25V@0.2A,1.8V..1.8V,2%,[ ],5.5V,0.2A,0.5W,315-0620-000; CDS_PHYS_PART_NAME: U_VREG_5PIN_SOT235-TLV70018,LOW DROP OUT/FIXED,0.25V@0.2A,1.8V..1.8V,2%,[ ],5.5V,0.2A,0.5W,315-0620-000-315-0620-000,[ ]; CDS_SEC: 1; DEVICE_TYPENAME: U_VREG_5PIN_SOT235-TLV70018LOWDROPOUTFIXED025V02A18V18V255V02A05W315-0620-000-315-0620-000; DRAWING: #NAME?; FORWARD_VOLTAGE: 0.25V@0.2A; MAX_CURRENT: 0.2A; MAX_VOLTAGE: 5.5V; MAX_WATTAGE: 0.5W; NV_NAME: TLV70018; NV_PN: 315-0620-000; OUTPUT_VOLTAGE: 1.8V..1.8V; PACK_TYPE: SOT235; PATH: I1; PHYS_PAGE: 10; ROT: 0; SEC: 1; TOL: 2%; TYPE: Low Drop Out/Fixed; VER: 15; XY: (-6250,5000)
U6 = U_LDO: ASSEMBLY: 3V3_AO; CDS_LIB: power_supply; CDS_PART_NAME: U_LDO_SOT23_5_NOVR-GS7116S5-ADJ-R,STANDARD,0.45V@0.5A,0.8V..5V,2%,0.8V,6.5V,0.5A,0.4W,315-1022-000; CDS_PHYS_PART_NAME: U_LDO_SOT23_5_NOVR-GS7116S5-ADJ-R,STANDARD,0.45V@0.5A,0.8V..5V,2%,0.8V,6.5V,0.5A,0.4W,315-1022-000-0.8V,315-1022-000; CDS_SEC: 1; DEVICE_TYPENAME: U_LDO_SOT23_5_NOVR-GS7116S5-ADJ-RSTANDARD045V05A08V5V208V65V05A04W315-1022-000-08V315-1022-000; DRAWING: #NAME?; FORWARD_VOLTAGE: 0.45V@0.5A; MAX_CURRENT: 0.5A; MAX_VOLTAGE: 6.5V; MAX_WATTAGE: 0.4W; NV_NAME: GS7116S5-ADJ-R; NV_PN: 315-1022-000; OUTPUT_VOLTAGE: 0.8V..5V; PACK_TYPE: SOT23_5_NOVR; PATH: I10; PHYS_PAGE: 10; ROT: 0; SEC: 1; TOL: 2%; TYPE: Standard; VER: 3; XY: (-6250,3350)
C135 = C#1_v2: ASSEMBLY: BUTTON_MCU; CDS_LIB: discrete; CDS_PART_NAME: C_0402-0.1UF,X5R,10%,6.3V,039-0007-000; CDS_PHYS_PART_NAME: C_0402-0.1UF,X5R,10%,6.3V,039-0007-000-0.1UF,039-0007-000; CDS_SEC: 1; CHIPS_PART_NAME: C; DEVICE_TYPENAME: C_0402-01UFX5R1063V039-0007-000-01UF039-0007-000; DRAWING: #NAME?; MAT: X5R; MAX_VOLTAGE: 6.3V; NV_PN: 039-0007-000; PATH: I27; PHYS_PAGE: 11; ROT: 0; SEC: 1; SIGNAL_MODEL: nv_cap; TOL: 10%; VER: 1; XY: (-8300,4850)
C142 = C#1_v2: ASSEMBLY: BUTTON_MCU; CDS_LIB: discrete; CDS_PART_NAME: C_0402-0.1UF,X5R,10%,6.3V,039-0007-000; CDS_PHYS_PART_NAME: C_0402-0.1UF,X5R,10%,6.3V,039-0007-000-0.1UF,039-0007-000; CDS_SEC: 1; CHIPS_PART_NAME: C; DEVICE_TYPENAME: C_0402-01UFX5R1063V039-0007-000-01UF039-0007-000; DRAWING: #NAME?; MAT: X5R; MAX_VOLTAGE: 6.3V; NV_PN: 039-0007-000; PATH: I49; PHYS_PAGE: 11; ROT: 0; SEC: 1; SIGNAL_MODEL: nv_cap; TOL: 10%; VER: 1; XY: (-4100,5600)
C169 = C#1_v2: ASSEMBLY: BUTTON_MCU; CDS_LIB: discrete; CDS_PART_NAME: C_0402-10NF,X5R,10%,16V,039-0024-000; CDS_PHYS_PART_NAME: C_0402-10NF,X5R,10%,16V,039-0024-000-039-0024-000,10NF; CDS_SEC: 1; CHIPS_PART_NAME: C; DEVICE_TYPENAME: C_0402-10NFX5R1016V039-0024-000-039-0024-00010NF; DRAWING: #NAME?; MAT: X5R; MAX_VOLTAGE: 16V; NV_PN: 039-0024-000; PATH: I82; PHYS_PAGE: 11; ROT: 0; SEC: 1; SIGNAL_MODEL: nv_cap; TOL: 10%; VER: 1; XY: (-2700,2400)
D62 = D_3PIN_CC: ASSEMBLY: BUTTON_MCU; CDS_LIB: discrete; CDS_PART_NAME: D_3PIN_CC_SOT323-BAT54CW,1 PAIR - COMMON CATHODE,30V,0.6A,1V@0.1A,0.2A,091-0022-000; CDS_PHYS_PART_NAME: D_3PIN_CC_SOT323-BAT54CW,1 PAIR - COMMON CATHODE,30V,0.6A,1V@0.1A,0.2A,091-0022-000-091-0022-000; CDS_SEC: 1; CONFIGURATION: 1 Pair - Common Cathode; CONTINUOUS_CURRENT: 0.2A; DEVICE_TYPENAME: D_3PIN_CC_SOT323-BAT54CW1PAIR-COMMONCATHODE30V06A1V01A02A091-0022-000-091-0022-000; DRAWING: #NAME?; FORWARD_VOLTAGE: 1V@0.1A; MAX_CURRENT: 0.6A; MAX_VOLTAGE: 30V; NV_NAME: BAT54CW; NV_PN: 091-0022-000; PATH: I57; PHYS_PAGE: 11; ROT: 2; SEC: 1; VER: 1; XY: (-3200,3650)
D63 = D_3PIN_CC: ASSEMBLY: BUTTON_MCU; CDS_LIB: discrete; CDS_PART_NAME: D_3PIN_CC_SOT323-BAT54CW,1 PAIR - COMMON CATHODE,30V,0.6A,1V@0.1A,0.2A,091-0022-000; CDS_PHYS_PART_NAME: D_3PIN_CC_SOT323-BAT54CW,1 PAIR - COMMON CATHODE,30V,0.6A,1V@0.1A,0.2A,091-0022-000-091-0022-000; CDS_SEC: 1; CONFIGURATION: 1 Pair - Common Cathode; CONTINUOUS_CURRENT: 0.2A; DEVICE_TYPENAME: D_3PIN_CC_SOT323-BAT54CW1PAIR-COMMONCATHODE30V06A1V01A02A091-0022-000-091-0022-000; DRAWING: #NAME?; FORWARD_VOLTAGE: 1V@0.1A; MAX_CURRENT: 0.6A; MAX_VOLTAGE: 30V; NV_NAME: BAT54CW; NV_PN: 091-0022-000; PATH: I58; PHYS_PAGE: 11; ROT: 2; SEC: 1; VER: 1; XY: (-2900,4650)
D66 = D_ZENER: ASSEMBLY: BUTTON_MCU; CDS_LIB: discrete; CDS_PART_NAME: D_ZENER_SOD523-BZT52C3V3T,3.5V,5MA,0.9V@10MA,0.3W,090-0343-000; CDS_PHYS_PART_NAME: D_ZENER_SOD523-BZT52C3V3T,3.5V,5MA,0.9V@10MA,0.3W,090-0343-000-090-0343-000; CDS_SEC: 1; CONTINUOUS_CURRENT: 0.3W; DEVICE_TYPENAME: D_ZENER_SOD523-BZT52C3V3T35V5MA09V10MA03W090-0343-000-090-0343-000; DRAWING: #NAME?; FORWARD_VOLTAGE: 0.9V@10mA; MAX_CURRENT: 5mA; MAX_VOLTAGE: 3.5V; NV_NAME: BZT52C3V3T; NV_PN: 090-0343-000; PACK_TYPE: SOD523; PATH: I91; PHYS_PAGE: 11; ROT: 0; SEC: 1; VER: 2; XY: (-3600,2400)
Q28 = Q_FET_P_ENH#1: ASSEMBLY: BUTTON_MCU; CDS_LIB: discrete; CDS_PART_NAME: Q_FET_P_ENH_SOT323_1G1D1S-BSS84W-7-F,-50V,-1000MOHM@10V / -1000MOHM@4.5V / -1000MOHM@2.5V,-0.13A,[ ],20V,0.2W,[ ]@10V / [ ]@4.A; CDS_PHYS_PART_NAME: Q_FET_P_ENH_SOT323_1G1D1S-BSS84W-7-F,-50V,-1000MOHM@10V / -1000MOHM@4.5V / -1000MOHM@2.5V,-0.13A,[ ],20V,0.2W,[ ]@10V / [ ]@4.B; CDS_SEC: 1; CONTINUOUS_CURRENT: -0.13A; DEVICE_TYPENAME: Q_FET_P_ENH_SOT323_1G1D1S-BSS84W-7-F-50V-1000MOHM10V-1000MOHM45V-1000MOHM25V-013A20V02W10V4B; DRAWING: #NAME?; MAX_CURRENT: [ ]; MAX_VOLTAGE: -50V; MAX_WATTAGE: 0.2W; NV_NAME: BSS84W-7-F; NV_PN: 300-0518-000; PACK_TYPE: SOT323_1G1D1S; PATH: I78; PHYS_PAGE: 11; Q_G: [ ]@10V / [ ]@4.5V / [ ]@2.5V; ROT: 3; R_DS_ON: -1000mohm@10V / -1000mohm@4.5V / -1000mohm@2.5V; SEC: 1; VER: 2; V_BE_GS: 20V; XY: (-2500,3150)
Q29 = Q_FET_N_ENH#1: ASSEMBLY: BUTTON_MCU; CDS_LIB: discrete; CDS_PART_NAME: Q_FET_N_ENH_SOT323_1G1D1S-2N7002_SERIES,60V,13500MOHM@10V / 7500MOHM@4.5V / [ ]@2.5V,0.115A,0.8A,20V,0.15W,[ ]@10V / 0.5NC@4.5A; CDS_PHYS_PART_NAME: Q_FET_N_ENH_SOT323_1G1D1S-2N7002_SERIES,60V,13500MOHM@10V / 7500MOHM@4.5V / [ ]@2.5V,0.115A,0.8A,20V,0.15W,[ ]@10V / 0.5NC@4.5B; CDS_SEC: 1; CONTINUOUS_CURRENT: 0.115A; CaptureCellPackProp: Q_FET_N_ENH##1; DEVICE_TYPENAME: Q_FET_N_ENH_SOT323_1G1D1S-2N7002_SERIES60V13500MOHM10V7500MOHM45V25V0115A08A20V015W10V05NC45B; DRAWING: #NAME?; MAX_CURRENT: 0.8A; MAX_VOLTAGE: 60V; MAX_WATTAGE: 0.15W; NV_NAME: 2N7002_SERIES; NV_PN: 300-1133-000; PACK_TYPE: SOT323_1G1D1S; PATH: I89; PHYS_PAGE: 11; Q_G: [ ]@10V / 0.5nC@4.5V / [ ]@2.5V; ROT: 2; R_DS_ON: 13500mohm@10V / 7500mohm@4.5V / [ ]@2.5V; SEC: 1; VER: 2; V_BE_GS: 20V; XY: (-1550,2750)
R137 = R#1: ASSEMBLY: BUTTON_MCU; CDS_LIB: discrete; CDS_PART_NAME: R_0402-10K,1 %,62.5MW,195-0004-000; CDS_PHYS_PART_NAME: R_0402-10K,1 %,62.5MW,195-0004-000-10K,195-0004-000; CDS_SEC: 1; CHIPS_PART_NAME: R; DEVICE_TYPENAME: R_0402-10K1625MW195-0004-000-10K195-0004-000; DRAWING: #NAME?; MAX_WATTAGE: 62.5mW; NV_PN: 195-0004-000; PATH: I36; PHYS_PAGE: 11; ROT: 2; SEC: 1; SIGNAL_MODEL: nv_res; SKU: NO STUFF; TOL: 1%; VER: 1; XY: (-8300,4100)
R138 = R: ASSEMBLY: BUTTON_MCU; CDS_LIB: discrete; CDS_PART_NAME: R_0402-100K,1 %,62.5MW,195-0005-000; CDS_PHYS_PART_NAME: R_0402-100K,1 %,62.5MW,195-0005-000-100K,195-0005-000; CDS_SEC: 1; DEVICE_TYPENAME: R_0402-100K1625MW195-0005-000-100K195-0005-000; DRAWING: #NAME?; MAX_WATTAGE: 62.5mW; NV_PN: 195-0005-000; PATH: I31; PHYS_PAGE: 11; ROT: 2; SEC: 1; SIGNAL_MODEL: nv_res; TOL: 1%; VER: 2; XY: (-7700,3550)
R139 = R: ASSEMBLY: BUTTON_MCU; CDS_LIB: discrete; CDS_PART_NAME: R_0402-10K,1 %,62.5MW,195-0004-000; CDS_PHYS_PART_NAME: R_0402-10K,1 %,62.5MW,195-0004-000-10K,195-0004-000; CDS_SEC: 1; DEVICE_TYPENAME: R_0402-10K1625MW195-0004-000-10K195-0004-000; DRAWING: #NAME?; MAX_WATTAGE: 62.5mW; NV_PN: 195-0004-000; PATH: I24; PHYS_PAGE: 11; ROT: 2; SEC: 1; SIGNAL_MODEL: nv_res; TOL: 1%; VER: 2; XY: (-7300,4850)
R140 = R: ASSEMBLY: BUTTON_MCU; CDS_LIB: discrete; CDS_PART_NAME: R_0402-4.7K,5 %,62.5MW,195-0598-000; CDS_PHYS_PART_NAME: R_0402-4.7K,5 %,62.5MW,195-0598-000-195-0598-000,4.7K; CDS_SEC: 1; DEVICE_TYPENAME: R_0402-47K5625MW195-0598-000-195-0598-00047K; DRAWING: #NAME?; MAX_WATTAGE: 62.5mW; NV_PN: 195-0598-000; PATH: I21; PHYS_PAGE: 11; ROT: 2; SEC: 1; SIGNAL_MODEL: nv_res; TOL: 5%; VER: 2; XY: (-6950,4850)
R141 = R: ASSEMBLY: BUTTON_MCU; CDS_LIB: discrete; CDS_PART_NAME: R_0402-10K,1 %,62.5MW,195-0004-000; CDS_PHYS_PART_NAME: R_0402-10K,1 %,62.5MW,195-0004-000-10K,195-0004-000; CDS_SEC: 1; DEVICE_TYPENAME: R_0402-10K1625MW195-0004-000-10K195-0004-000; DRAWING: #NAME?; MAX_WATTAGE: 62.5mW; NV_PN: 195-0004-000; PATH: I18; PHYS_PAGE: 11; ROT: 2; SEC: 1; SIGNAL_MODEL: nv_res; TOL: 1%; VER: 2; XY: (-5700,5200)
R142 = R: ASSEMBLY: BUTTON_MCU; CDS_LIB: discrete; CDS_PART_NAME: R_0402-19.6K,1 %,62.5MW,195-0145-000; CDS_PHYS_PART_NAME: R_0402-19.6K,1 %,62.5MW,195-0260-000-195-0145-000,34K; CDS_SEC: 1; DEVICE_TYPENAME: R_0402-34K1625MW195-0260-000-195-0260-00034K; DRAWING: #NAME?; MAX_WATTAGE: 62.5mW; NV_PN: 195-0145-000; PATH: I6; PHYS_PAGE: 11; ROT: 2; SEC: 1; SIGNAL_MODEL: nv_res; TOL: 1%; VER: 2; XY: (-2900,2900)
R144 = R: ASSEMBLY: BUTTON_MCU; CDS_LIB: discrete; CDS_PART_NAME: R_0402-100K,1 %,62.5MW,195-0005-000; CDS_PHYS_PART_NAME: R_0402-100K,1 %,62.5MW,195-0005-000-100K,195-0005-000; CDS_SEC: 1; DEVICE_TYPENAME: R_0402-100K1625MW195-0005-000-100K195-0005-000; DRAWING: #NAME?; MAX_WATTAGE: 62.5mW; NV_PN: 195-0005-000; PATH: I5; PHYS_PAGE: 11; ROT: 2; SEC: 1; SIGNAL_MODEL: nv_res; TOL: 1%; VER: 2; XY: (-4200,6000)
R165 = R#1: ASSEMBLY: BUTTON_MCU; CDS_LIB: discrete; CDS_PART_NAME: R_0402-110OHM,5 %,62.5MW,195-0492-000; CDS_PHYS_PART_NAME: R_0402-110OHM,5 %,62.5MW,195-0492-000-110OHM,195-0492-000; CDS_SEC: 1; CHIPS_PART_NAME: R; DEVICE_TYPENAME: R_0402-110OHM5625MW195-0492-000-110OHM195-0492-000; DRAWING: #NAME?; MAX_WATTAGE: 62.5mW; NV_PN: 195-0492-000; PATH: I56; PHYS_PAGE: 11; ROT: 0; SEC: 1; TOL: 5%; VER: 1; XY: (-3700,5750)
R166 = R: ASSEMBLY: BUTTON_MCU; CDS_LIB: discrete; CDS_PART_NAME: R_0402-100K,1 %,62.5MW,195-0005-000; CDS_PHYS_PART_NAME: R_0402-100K,1 %,62.5MW,195-0005-000-100K,195-0005-000; CDS_SEC: 1; DEVICE_TYPENAME: R_0402-100K1625MW195-0005-000-100K195-0005-000; DRAWING: #NAME?; MAX_WATTAGE: 62.5mW; NV_PN: 195-0005-000; PATH: I66; PHYS_PAGE: 11; ROT: 2; SEC: 1; SIGNAL_MODEL: nv_res; TOL: 1%; VER: 2; XY: (-10900,4050)
R170 = R: ASSEMBLY: BUTTON_MCU; CDS_LIB: discrete; CDS_PART_NAME: R_0402-100K,1 %,62.5MW,195-0005-000; CDS_PHYS_PART_NAME: R_0402-100K,1 %,62.5MW,195-0005-000-100K,195-0005-000; CDS_SEC: 1; DEVICE_TYPENAME: R_0402-100K1625MW195-0005-000-100K195-0005-000; DRAWING: #NAME?; MAX_WATTAGE: 62.5mW; NV_PN: 195-0005-000; PATH: I61; PHYS_PAGE: 11; ROT: 0; SEC: 1; TOL: 1%; VER: 2; XY: (-1850,3900)
R183 = R: ASSEMBLY: BUTTON_MCU; CDS_LIB: discrete; CDS_PART_NAME: R_0402-10K,1 %,62.5MW,195-0004-000; CDS_PHYS_PART_NAME: R_0402-10K,1 %,62.5MW,195-0004-000-10K,195-0004-000; CDS_SEC: 1; DEVICE_TYPENAME: R_0402-10K1625MW195-0004-000-10K195-0004-000; DRAWING: #NAME?; MAX_WATTAGE: 62.5mW; NV_PN: 195-0004-000; PATH: I75; PHYS_PAGE: 11; ROT: 2; SEC: 1; SIGNAL_MODEL: nv_res; TOL: 1%; VER: 2; XY: (-5450,5200)
R184 = R: ASSEMBLY: BUTTON_MCU; CDS_LIB: discrete; CDS_PART_NAME: R_0402-10K,1 %,62.5MW,195-0004-000; CDS_PHYS_PART_NAME: R_0402-10K,1 %,62.5MW,195-0004-000-10K,195-0004-000; CDS_SEC: 1; DEVICE_TYPENAME: R_0402-10K1625MW195-0004-000-10K195-0004-000; DRAWING: #NAME?; MAX_WATTAGE: 62.5mW; NV_PN: 195-0004-000; PATH: I76; PHYS_PAGE: 11; ROT: 2; SEC: 1; SIGNAL_MODEL: nv_res; TOL: 1%; VER: 2; XY: (-5200,5200)
R195 = R: ASSEMBLY: BUTTON_MCU; CDS_LIB: discrete; CDS_PART_NAME: R_0402-5.11K,1 %,62.5MW,195-0344-000; CDS_PHYS_PART_NAME: R_0402-5.11K,1 %,62.5MW,195-0004-000-10K,195-0344-000; CDS_SEC: 1; DEVICE_TYPENAME: R_0402-10K1625MW195-0004-000-10K195-0004-000; DRAWING: #NAME?; MAX_WATTAGE: 62.5mW; NV_PN: 195-0344-000; PATH: I77; PHYS_PAGE: 11; ROT: 2; SEC: 1; SIGNAL_MODEL: nv_res; TOL: 1%; VER: 2; XY: (-2900,2400)
R196 = R#1: ASSEMBLY: BUTTON_MCU; CDS_LIB: discrete; CDS_PART_NAME: R_0402-100K,1 %,62.5MW,195-0005-000; CDS_PHYS_PART_NAME: R_0402-100K,1 %,62.5MW,195-0005-000-100K,195-0005-000; CDS_SEC: 1; CHIPS_PART_NAME: R; DEVICE_TYPENAME: R_0402-100K1625MW195-0005-000-100K195-0005-000; DRAWING: #NAME?; MAX_WATTAGE: 62.5mW; NV_PN: 195-0005-000; PATH: I80; PHYS_PAGE: 11; ROT: 2; SEC: 1; SIGNAL_MODEL: nv_res; TOL: 1%; VER: 1; XY: (-1200,3300)
R197 = R: ASSEMBLY: BUTTON_MCU; CDS_LIB: discrete; CDS_PART_NAME: R_0402-100K,1 %,62.5MW,195-0005-000; CDS_PHYS_PART_NAME: R_0402-100K,1 %,62.5MW,195-0005-000-100K,195-0005-000; CDS_SEC: 1; DEVICE_TYPENAME: R_0402-100K1625MW195-0005-000-100K195-0005-000; DRAWING: #NAME?; MAX_WATTAGE: 62.5mW; NV_PN: 195-0005-000; PATH: I87; PHYS_PAGE: 11; ROT: 2; SEC: 1; SIGNAL_MODEL: nv_res; TOL: 1%; VER: 2; XY: (-1100,2400)
R198 = R: ASSEMBLY: BUTTON_MCU; CDS_LIB: discrete; CDS_PART_NAME: R_0402-10K,1 %,62.5MW,195-0004-000; CDS_PHYS_PART_NAME: R_0402-10K,1 %,62.5MW,195-0004-000-10K,195-0004-000; CDS_SEC: 1; DEVICE_TYPENAME: R_0402-10K1625MW195-0004-000-10K195-0004-000; DRAWING: #NAME?; MAX_WATTAGE: 62.5mW; NV_PN: 195-0004-000; PATH: I90; PHYS_PAGE: 11; ROT: 2; SEC: 1; SIGNAL_MODEL: nv_res; SKU: NO STUFF; TOL: 1%; VER: 2; XY: (-4950,5200)
R203 = R: ASSEMBLY: BUTTON_MCU; CDS_LIB: discrete; CDS_PART_NAME: R_0402-100K,1 %,62.5MW,195-0005-000; CDS_PHYS_PART_NAME: R_0402-100K,1 %,62.5MW,195-0005-000-100K,195-0005-000; CDS_SEC: 1; DEVICE_TYPENAME: R_0402-100K1625MW195-0005-000-100K195-0005-000; DRAWING: #NAME?; MAX_WATTAGE: 62.5mW; NV_PN: 195-0005-000; PATH: I94; PHYS_PAGE: 11; ROT: 0; SEC: 1; TOL: 1%; VER: 2; XY: (-4400,2600)
R224 = R: ASSEMBLY: BUTTON_MCU; CDS_LIB: discrete; CDS_PART_NAME: R_0402-10K,1 %,62.5MW,195-0004-000; CDS_PHYS_PART_NAME: R_0402-10K,1 %,62.5MW,195-0004-000-10K,195-0004-000; CDS_SEC: 1; DEVICE_TYPENAME: R_0402-10K1625MW195-0004-000-10K195-0004-000; DRAWING: #NAME?; MAX_WATTAGE: 62.5mW; NV_PN: 195-0004-000; PATH: I101; PHYS_PAGE: 11; ROT: 2; SEC: 1; SIGNAL_MODEL: nv_res; TOL: 1%; VER: 2; XY: (-4650,5200)
R225 = R#1: ASSEMBLY: BUTTON_MCU; CDS_LIB: discrete; CDS_PART_NAME: R_0402-0OHM,0.05 OHM,62.5MW,195-2655-000; CDS_PHYS_PART_NAME: R_0402-0OHM,0.05 OHM,62.5MW,195-2655-000-0OHM,195-2655-000; CDS_SEC: 1; CHIPS_PART_NAME: R; DEVICE_TYPENAME: R_0402-0OHM005OHM625MW195-2655-000-0OHM195-2655-000; DRAWING: #NAME?; MAX_WATTAGE: 62.5mW; NV_PN: 195-2655-000; PATH: I102; PHYS_PAGE: 11; ROT: 0; SEC: 1; SKU: NO STUFF; TOL: 0.05 ohm; VER: 1; XY: (-4450,3950)
R226 = R: ASSEMBLY: BUTTON_MCU; CDS_LIB: discrete; CDS_PART_NAME: R_0402-91K,5 %,62.5MW,195-0648-000; CDS_PHYS_PART_NAME: R_0402-91K,5 %,62.5MW,195-0648-000-195-0648-000,91K; CDS_SEC: 1; DEVICE_TYPENAME: R_0402-91K5625MW195-0648-000-195-0648-00091K; DRAWING: #NAME?; MAX_WATTAGE: 62.5mW; NV_PN: 195-0648-000; PATH: I103; PHYS_PAGE: 11; ROT: 0; SEC: 1; TOL: 5%; VER: 2; XY: (-1650,3100)
R227 = R#1: ASSEMBLY: BUTTON_MCU; CDS_LIB: discrete; CDS_PART_NAME: R_0402-10K,1 %,62.5MW,195-0004-000; CDS_PHYS_PART_NAME: R_0402-10K,1 %,62.5MW,195-0004-000-10K,195-0004-000; CDS_SEC: 1; CHIPS_PART_NAME: R; DEVICE_TYPENAME: R_0402-10K1625MW195-0004-000-10K195-0004-000; DRAWING: #NAME?; MAX_WATTAGE: 62.5mW; NV_PN: 195-0004-000; PATH: I104; PHYS_PAGE: 11; ROT: 2; SEC: 1; SIGNAL_MODEL: nv_res; SKU: NO STUFF; TOL: 1%; VER: 1; XY: (-5200,4350)
R228 = R#1: ASSEMBLY: BUTTON_MCU; CDS_LIB: discrete; CDS_PART_NAME: R_0402-10K,1 %,62.5MW,195-0004-000; CDS_PHYS_PART_NAME: R_0402-10K,1 %,62.5MW,195-0004-000-10K,195-0004-000; CDS_SEC: 1; CHIPS_PART_NAME: R; DEVICE_TYPENAME: R_0402-10K1625MW195-0004-000-10K195-0004-000; DRAWING: #NAME?; MAX_WATTAGE: 62.5mW; NV_PN: 195-0004-000; PATH: I105; PHYS_PAGE: 11; ROT: 2; SEC: 1; SIGNAL_MODEL: nv_res; SKU: NO STUFF; TOL: 1%; VER: 1; XY: (-5200,4150)
TP9 = LABTESTPOINT#1: CDS_LIB: electro_mechanic; CDS_PART_NAME: LABTESTPOINT_PIN-LABTESTPOINT; CDS_PHYS_PART_NAME: LABTESTPOINT_PIN-LABTESTPOINT; CDS_SEC: 1; DEVICE_TYPENAME: LABTESTPOINT_PIN-LABTESTPOINT; DRAWING: #NAME?; PACK_TYPE: PIN; PATH: I41; PHYS_PAGE: 11; ROT: 0; SEC: 1; VER: 1; XY: (-8800,3900)
TP10 = LABTESTPOINT#1: CDS_LIB: electro_mechanic; CDS_PART_NAME: LABTESTPOINT_PIN-LABTESTPOINT; CDS_PHYS_PART_NAME: LABTESTPOINT_PIN-LABTESTPOINT; CDS_SEC: 1; DEVICE_TYPENAME: LABTESTPOINT_PIN-LABTESTPOINT; DRAWING: #NAME?; PACK_TYPE: PIN; PATH: I42; PHYS_PAGE: 11; ROT: 0; SEC: 1; VER: 1; XY: (-8800,3800)
TP11 = LABTESTPOINT#1: CDS_LIB: electro_mechanic; CDS_PART_NAME: LABTESTPOINT_PIN-LABTESTPOINT; CDS_PHYS_PART_NAME: LABTESTPOINT_PIN-LABTESTPOINT; CDS_SEC: 1; DEVICE_TYPENAME: LABTESTPOINT_PIN-LABTESTPOINT; DRAWING: #NAME?; PACK_TYPE: PIN; PATH: I43; PHYS_PAGE: 11; ROT: 0; SEC: 1; VER: 1; XY: (-8800,3750)
TP12 = LABTESTPOINT: CDS_LIB: electro_mechanic; CDS_PART_NAME: LABTESTPOINT_PIN-LABTESTPOINT; CDS_PHYS_PART_NAME: LABTESTPOINT_PIN-LABTESTPOINT; CDS_SEC: 1; DEVICE_TYPENAME: LABTESTPOINT_PIN-LABTESTPOINT; DRAWING: #NAME?; PACK_TYPE: PIN; PATH: I22; PHYS_PAGE: 11; ROT: 0; SEC: 1; VER: 3; XY: (-4850,4250)
U18 = U_CPU_EFM8SB1: ASSEMBLY: BUTTON_MCU; CDS_LIB: digital; CDS_PART_NAME: U_CPU_EFM8SB1_QFN20-EFM8SB10F2G,OTHER,115-2594-000; CDS_PHYS_PART_NAME: U_CPU_EFM8SB1_QFN20-EFM8SB10F2G,OTHER,115-2594-000-115-2594-000; CDS_SEC: 1; DEVICE_TYPENAME: U_CPU_EFM8SB1_QFN20-EFM8SB10F2GOTHER115-2594-000-115-2594-000; DRAWING: #NAME?; NV_NAME: EFM8SB10F2G; NV_PN: 115-2594-000; PACK_TYPE: QFN20; PATH: I1; PHYS_PAGE: 11; ROT: 0; SEC: 1; TYPE: Other; VER: 1; XY: (-6350,4050)
U19 = U_BUF_OD: ASSEMBLY: BUTTON_MCU; CDS_LIB: logic; CDS_PART_NAME: U_BUF_OD_SC70_5-74LVC1G07GW/SN74LVC1G07DCKRE4,BUFFER - OPEN DRAIN,115-0138-000; CDS_PHYS_PART_NAME: U_BUF_OD_SC70_5-74LVC1G07GW/SN74LVC1G07DCKRE4,BUFFER - OPEN DRAIN,115-0138-000-115-0138-000; CDS_SEC: 1; DEVICE_TYPENAME: U_BUF_OD_SC70_5-74LVC1G07GWSN74LVC1G07DCKRE4BUFFER-OPENDRAIN115-0138-000-115-0138-000; DRAWING: #NAME?; FUNCTION: Buffer - Open Drain; NV_NAME: 74LVC1G07GW/SN74LVC1G07DCKRE4; NV_PN: 115-0138-000; PATH: I54; PHYS_PAGE: 11; ROT: 2; SEC: 1; VER: 1; XY: (-3000,5750)
U22 = U_LEVSHFT_3STATE: ASSEMBLY: BUTTON_MCU; CDS_LIB: logic; CDS_PART_NAME: U_LEVSHFT_3STATE_SC70_5-SN74LV1T125,LEVEL SHIFTER,115-2747-000; CDS_PHYS_PART_NAME: U_LEVSHFT_3STATE_SC70_5-SN74LV1T125,LEVEL SHIFTER,115-2747-000-115-2747-000; CDS_SEC: 1; DEVICE_TYPENAME: U_LEVSHFT_3STATE_SC70_5-SN74LV1T125LEVELSHIFTER115-2747-000-115-2747-000; DRAWING: #NAME?; FUNCTION: Level Shifter; NV_NAME: SN74LV1T125; NV_PN: 115-2747-000; PATH: I96; PHYS_PAGE: 11; ROT: 2; SEC: 1; VER: 10; XY: (-10250,4300)
U23 = U_LEVSHFT_3STATE: ASSEMBLY: BUTTON_MCU; CDS_LIB: logic; CDS_PART_NAME: U_LEVSHFT_3STATE_SC70_5-SN74LV1T125,LEVEL SHIFTER,115-2747-000; CDS_PHYS_PART_NAME: U_LEVSHFT_3STATE_SC70_5-SN74LV1T125,LEVEL SHIFTER,115-2747-000-115-2747-000; CDS_SEC: 1; DEVICE_TYPENAME: U_LEVSHFT_3STATE_SC70_5-SN74LV1T125LEVELSHIFTER115-2747-000-115-2747-000; DRAWING: #NAME?; FUNCTION: Level Shifter; NV_NAME: SN74LV1T125; NV_PN: 115-2747-000; PATH: I97; PHYS_PAGE: 11; ROT: 2; SEC: 1; VER: 10; XY: (-4950,2750)

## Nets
3V3_AO: C34.1 C36.1 C135.1 R30.1 R139.1 R140.1 R141.1 R144.1 R183.1 R184.1 R198.1 R224.1 U6.5(OUT) U18.4(VDD) U19.5(VCC) U23.5(VCC)
3V3_AO_ADJ: C34.2 R30.2 R31.1 U6.4(ADJ)
5V_PG_BUF_R: R165.2 U19.4(Y)
GND: C19.2 C20.2 C21.2 C22.2 C23.2 C27.2 C28.2 C30.2 C31.2 C32.2 C33.2 C35.2 C36.2 C135.2 C142.2 C150.2 C151.2 C169.2 C175.2 D66.2(A) Q7.1(S1) Q7.2(S2) Q7.3(S3) Q29.2(S) Q36.2(S) Q37.2(S) R25.2 R28.2 R31.2 R137.2 R138.2 R166.2 R195.2 R197.2 R203.2 R227.1 R228.1 TP11.1 U4.6(PGND) U5.2(GND1) U5.4(GND2) U6.2(GND) U18.3(GND1) U18.12(GND2) U18.21(EPAD) U19.3(GND) U22.1(OE*) U22.3(GND) U23.1(OE*) U23.3(GND) ; also on sheet 1 2 3 4 5 6 7 8 9 10 11 12 13 17 18 19 21
VDD_1V8: C35.1 U5.5(OUT) ; also on sheet 2 3 4 5 8 9 19 21
VDD_3V3_DISCHG: Q37.3(D) R205.2
VDD_3V3_SYS: C27.1 C28.1 C33.1 C150.1 C151.1 C175.1 L5.2 L6.2 R26.1 R164.1 R205.1 U5.1(IN) ; also on sheet 2 3 4 5 6 7 8 9 12 19 20 21
VDD_5V_SYS: C30.1 C31.1 C32.1 R170.1 R204.1 U6.1(IN) U22.5(VCC) ; also on sheet 2 3 8 9 10 11 12 17 21
VDD_DCIN: C20.1 C21.1 C23.1 Q6.5(D) Q28.2(S) R196.1 U4.5(VIN) ; also on sheet 17 18
BMCU_ACOK: C142.1 R144.2 R165.1 U18.16(P0_6) ; also on sheet 2
BMCU_BRD_SEL: R137.1 R139.2 U18.11(P1_2)
BMCU_C2CK: R140.2 TP10.1 U18.5(RST*)
BMCU_C2D: TP9.1 U18.6(P2_7_C2D)
BMCU_P01: R183.2 U18.1(P0)
BMCU_P02: R184.2 U18.20(P0_2)
BMCU_P03: R227.2 U18.19(P0_3)
BMCU_P05: R228.2 U18.17(P0_5)
BMCU_PGOOD: R224.2 R225.1 U18.15(P0_7)
BMCU_POWER_EN: R138.1 U18.9(P1_5) U22.2(IN)
BMCU_PWR_BTN*: D63.1(A1) D63.2(A2) R141.2 U18.2(P0_0)
BMCU_UART_TX: TP12.1 U18.18(P0_4)
BUCK_3V3_BST: R23.1 U4.10(VBST)
BUCK_3V3_BST_R: C24.1 R23.2
BUCK_3V3_DRVH: Q6.4(G) U4.9(DRVH)
BUCK_3V3_DRVL: Q7.4(G) R25.1 U4.7(DRVL)
BUCK_3V3_EN: Q36.1(G) U4.4(EN) U18.13(P1_1) U23.4(OUT)
BUCK_3V3_FB: C26.2 R27.2 R28.1 U4.1(VFB)
BUCK_3V3_FB_MID: R26.2 R27.1 R29.1
BUCK_3V3_FB_MID_R: C26.1 R29.2
BUCK_3V3_PG: R164.2 R225.2 U4.2(PG) U5.3(EN) ; also on sheet 8 12
BUCK_3V3_SNUB: C22.1 R24.2
BUCK_3V3_SW: C24.2 L5.1 L6.1 Q6.1(S1) Q6.2(S2) Q6.3(S3) Q7.5(D) R24.1 U4.8(SW)
BUCK_3V3_VREG5: C19.1 U4.3(VREG5)
BUCK_5V_PG: Q29.1(G) R197.1 U6.3(EN) U19.2(A) ; also on sheet 17
DCJ_UNPLUG: Q28.1(G) R196.2 R226.1
DCJ_UNPLUG_Q: Q28.3(D) R142.1
DCJ_UNPLUG_R: Q29.3(D) R226.2
DISCHG_3V3_SYS: Q36.3(D) Q37.1(G) R204.2
FORCE_OFF*: C169.1 D62.1(A1) D62.2(A2) D66.1(K) R142.2 R195.1 R198.2 U18.14(P1_0)
POWER_EN: R166.1 U22.4(OUT) ; also on sheet 8 21
PWR_BTN*: D63.3(CC) ; also on sheet 2 21
SHUTDOWN_REQ*: D62.3(CC) R170.2 ; also on sheet 18 21
SNN_BMCU_P13: U18.10(P1_3)
SNN_BMCU_P17: U18.7(P1)
SNN_PWR_BTN_BUF*: U18.8(P1_6)
SYS_RST*: R203.1 U23.2(IN) ; also on sheet 2 21

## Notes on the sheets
sheet 14
- A
- B
- C
- D
- E
- F
- G
- H
- BUTTON MCU FOR POWER UP
- 1
- 1
- 10ms Delay
- 2
- 2
- open:auto ON
- short:manual ON
- 1:Galen/Xavier
  NX
- 0:Mystique
- 3
- 3
- STATE_DIAGRAM
- 4
- 4
- AS AN INDICATOR THAT THE MODULE HAS
- BUCK 3V3 POWER GOOD SIGNAL IS USED
- POWERED UP PROPERLY.
- HENCE, BUCK_3V3_PG IS TIED TO PGOOD OF
- BUTTON MCU.
- 5
- 5
- NVIDIA CORPORATION
- 2701 SAN TOMAS
  EXPRESSWAY
- ASSEMBLY
- <ASSEMBLY_DESCRIPTION>
- SANTA CLARA, CA 95050, USA
- PAGE DETAIL
- BUTTON MCU
- NV_PN
- 600-13509-BASE-100
- ALL NVIDIA DESIGN SPECIFICATIONS, REFERENCE SPECIFICATIONS, REFERENCE BOARDS, FILES, DRAWINGS, DIAGNOSTICS, LISTS AND OTHER DOCUMENTS OR INFORMATION (TOGETHER AND SEPARATELY, 'MATERIALS') ARE BEING PROVIDED 'AS IS'. THE MATERIALS
  MAY
- CONTAIN KNOWN AND UNKNOWN VIOLATIONS OR DEVIATIONS OF INDUSTRY STANDARDS AND SPECIFICATIONS. NVIDIA MAKES NO WARRANTIES, EXPRESSED, IMPLIED, STATUTORY OR OTHERWISE WITH RESPECT TO THE MATERIALS OR OTHERWISE, AND EXPRESSLY DISCLAIMS
  ALL
- PCB REV
- P3509-A01
- PAGE
- 11 OF 25
- IMPLIED WARRANTIES INCLUDING, WITHOUT LIMITATION, THE WARRANTIES OF DESIGN, OF NONINFRINGEMENT, MERCHANTABILITY OR FITNESS FOR A PARTICULAR PURPOSE, OR ARISING FROM A COURSE OF DEALING, TRADE USAGE, TRADE PRACTICE, OR INDUSTRY
  STANDARDS.
- BOM REV
- <BOM_REV>
- DATE
- 27-NOV-2019
- A
- B
- C
- D
- E
- F
- G
- H
sheet 15
- A
- B
- C
- D
- E
- F
- G
- H
- 1V8 LDO AND 3V3 A0 RAILS
- 1
- 1
- 1V8 LDO
- 2
- 2
- 3
- 3
- Rt
- Rb
- VOUT=VREF(0.8V)* (1+(RT/RB))+Iadj(1nA)*Rt
- RT=309k
- 4
- RB=100k
- 4
- VOUT=3.272V
- 5
- 5
- NVIDIA CORPORATION
- 2701 SAN TOMAS EXPRESSWAY
- ASSEMBLY
- <ASSEMBLY_DESCRIPTION>
- SANTA CLARA, CA 95050, USA
- PAGE DETAIL
- 1V8 LDO & 3V3 AO Rails
- NV_PN
- 600-13509-BASE-100
- ALL NVIDIA DESIGN SPECIFICATIONS, REFERENCE SPECIFICATIONS, REFERENCE BOARDS, FILES, DRAWINGS, DIAGNOSTICS, LISTS AND OTHER DOCUMENTS OR INFORMATION (TOGETHER AND SEPARATELY, 'MATERIALS') ARE BEING PROVIDED 'AS IS'. THE MATERIALS MAY
- CONTAIN KNOWN AND UNKNOWN VIOLATIONS OR DEVIATIONS OF INDUSTRY STANDARDS AND SPECIFICATIONS. NVIDIA MAKES NO WARRANTIES, EXPRESSED, IMPLIED, STATUTORY OR OTHERWISE WITH RESPECT TO THE MATERIALS OR OTHERWISE, AND EXPRESSLY DISCLAIMS ALL
- PCB REV
- P3509-A01
- PAGE
- 10 OF 25
- IMPLIED WARRANTIES INCLUDING, WITHOUT LIMITATION, THE WARRANTIES OF DESIGN, OF NONINFRINGEMENT, MERCHANTABILITY OR FITNESS FOR A PARTICULAR PURPOSE, OR ARISING FROM A COURSE OF DEALING, TRADE USAGE, TRADE PRACTICE, OR INDUSTRY STANDARDS.
- BOM REV
- <BOM_REV>
- DATE
- 27-NOV-2019
- A
- B
- C
- D
- E
- F
- G
- H
sheet 16
- A
- B
- C
- D
- E
- F
- G
- H
- PRE-REG 3V3 DCDC
- 1
- 1
- PCB CO-LAYOUT
- 2
- 2
- ROCL
- Rb1
- Iocl=(Vin-Vout)*Vout/(2*L*fsw*Vin)+Vtrip/Rdson
- Rb2
- 3
- take Vin(min) as an example
- 3
- Vout = Vref * ((Rb1 / Rb2) + 1)
- Vref = 0.773V
- Iocl=(9-3.3)*3.3/(2*1*0.5*9)+125/6.1=~20.5A
- Vout = 0.773 * ((90.9 / 27.4) + 1)=3.33V
- ESTIMATED TOTAL CURRENT
- M.2 WIFI/BT = 2.5A
- M.2 NVME    = 2.5A
- MISC        = 0.5A
- TOTAL       = 5.5A
- VDD_3V3_SYS RAIL DISCHARGE
- 4
- 4
- 5
- 5
- NVIDIA CORPORATION
- 2701 SAN TOMAS EXPRESSWAY
- ASSEMBLY
- <ASSEMBLY_DESCRIPTION>
- SANTA CLARA, CA 95050, USA
- PAGE DETAIL
- PRE-REG 3V3
- NV_PN
- 600-13509-BASE-100
- ALL NVIDIA DESIGN SPECIFICATIONS, REFERENCE SPECIFICATIONS, REFERENCE BOARDS, FILES, DRAWINGS, DIAGNOSTICS, LISTS AND OTHER DOCUMENTS OR INFORMATION (TOGETHER AND SEPARATELY, 'MATERIALS') ARE BEING PROVIDED 'AS IS'. THE MATERIALS MAY
- CONTAIN KNOWN AND UNKNOWN VIOLATIONS OR DEVIATIONS OF INDUSTRY STANDARDS AND SPECIFICATIONS. NVIDIA MAKES NO WARRANTIES, EXPRESSED, IMPLIED, STATUTORY OR OTHERWISE WITH RESPECT TO THE MATERIALS OR OTHERWISE, AND EXPRESSLY DISCLAIMS ALL
- PCB REV
- P3509-A01
- PAGE
- 9 OF 25
- IMPLIED WARRANTIES INCLUDING, WITHOUT LIMITATION, THE WARRANTIES OF DESIGN, OF NONINFRINGEMENT, MERCHANTABILITY OR FITNESS FOR A PARTICULAR PURPOSE, OR ARISING FROM A COURSE OF DEALING, TRADE USAGE, TRADE PRACTICE, OR INDUSTRY STANDARDS.
- BOM REV
- <BOM_REV>
- DATE
- 27-NOV-2019
- A
- B
- C
- D
- E
- F
- G
- H
